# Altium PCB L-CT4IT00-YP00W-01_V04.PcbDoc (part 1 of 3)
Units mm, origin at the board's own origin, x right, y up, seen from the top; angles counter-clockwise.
Board outline 45 x 50 mm, 6 copper layers (Top Layer, GND1, Signal3, Siganl4, GND5, Bottom Layer), stack 1.57 mm thick; 213 components, 129 nets, 723 pads, 573 vias.
Unrouted connection lines stored in the file: 173.
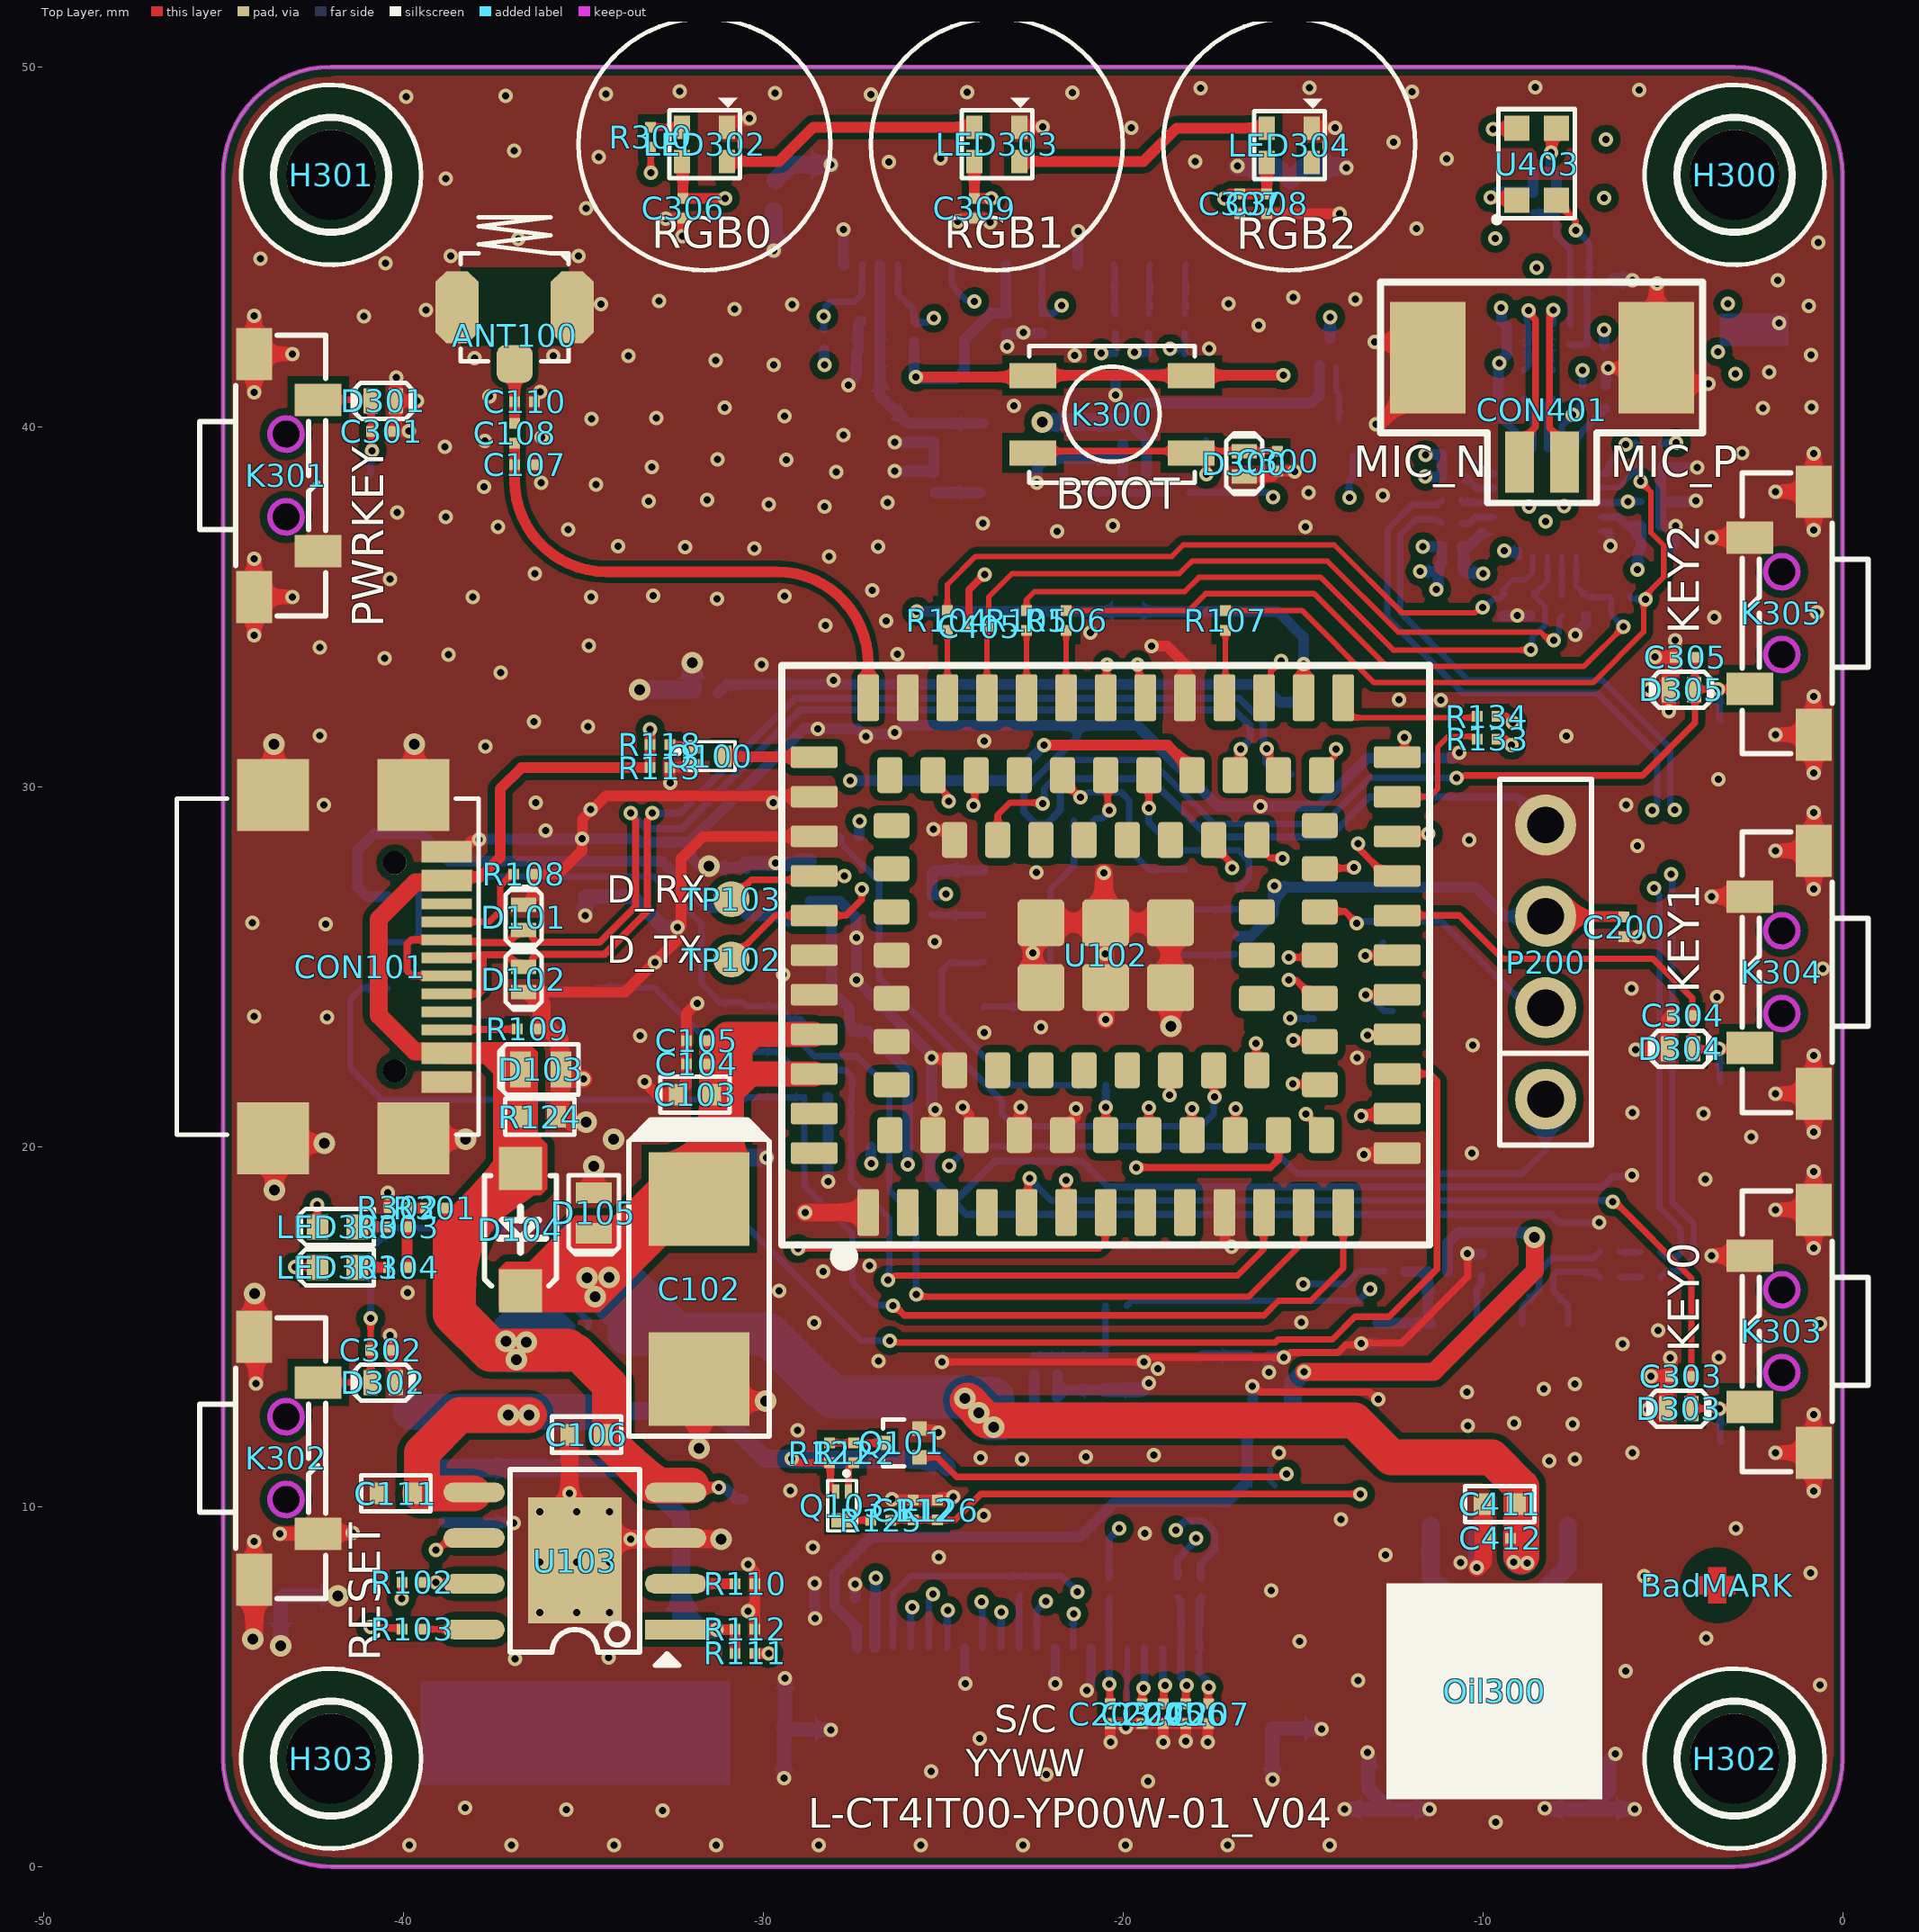
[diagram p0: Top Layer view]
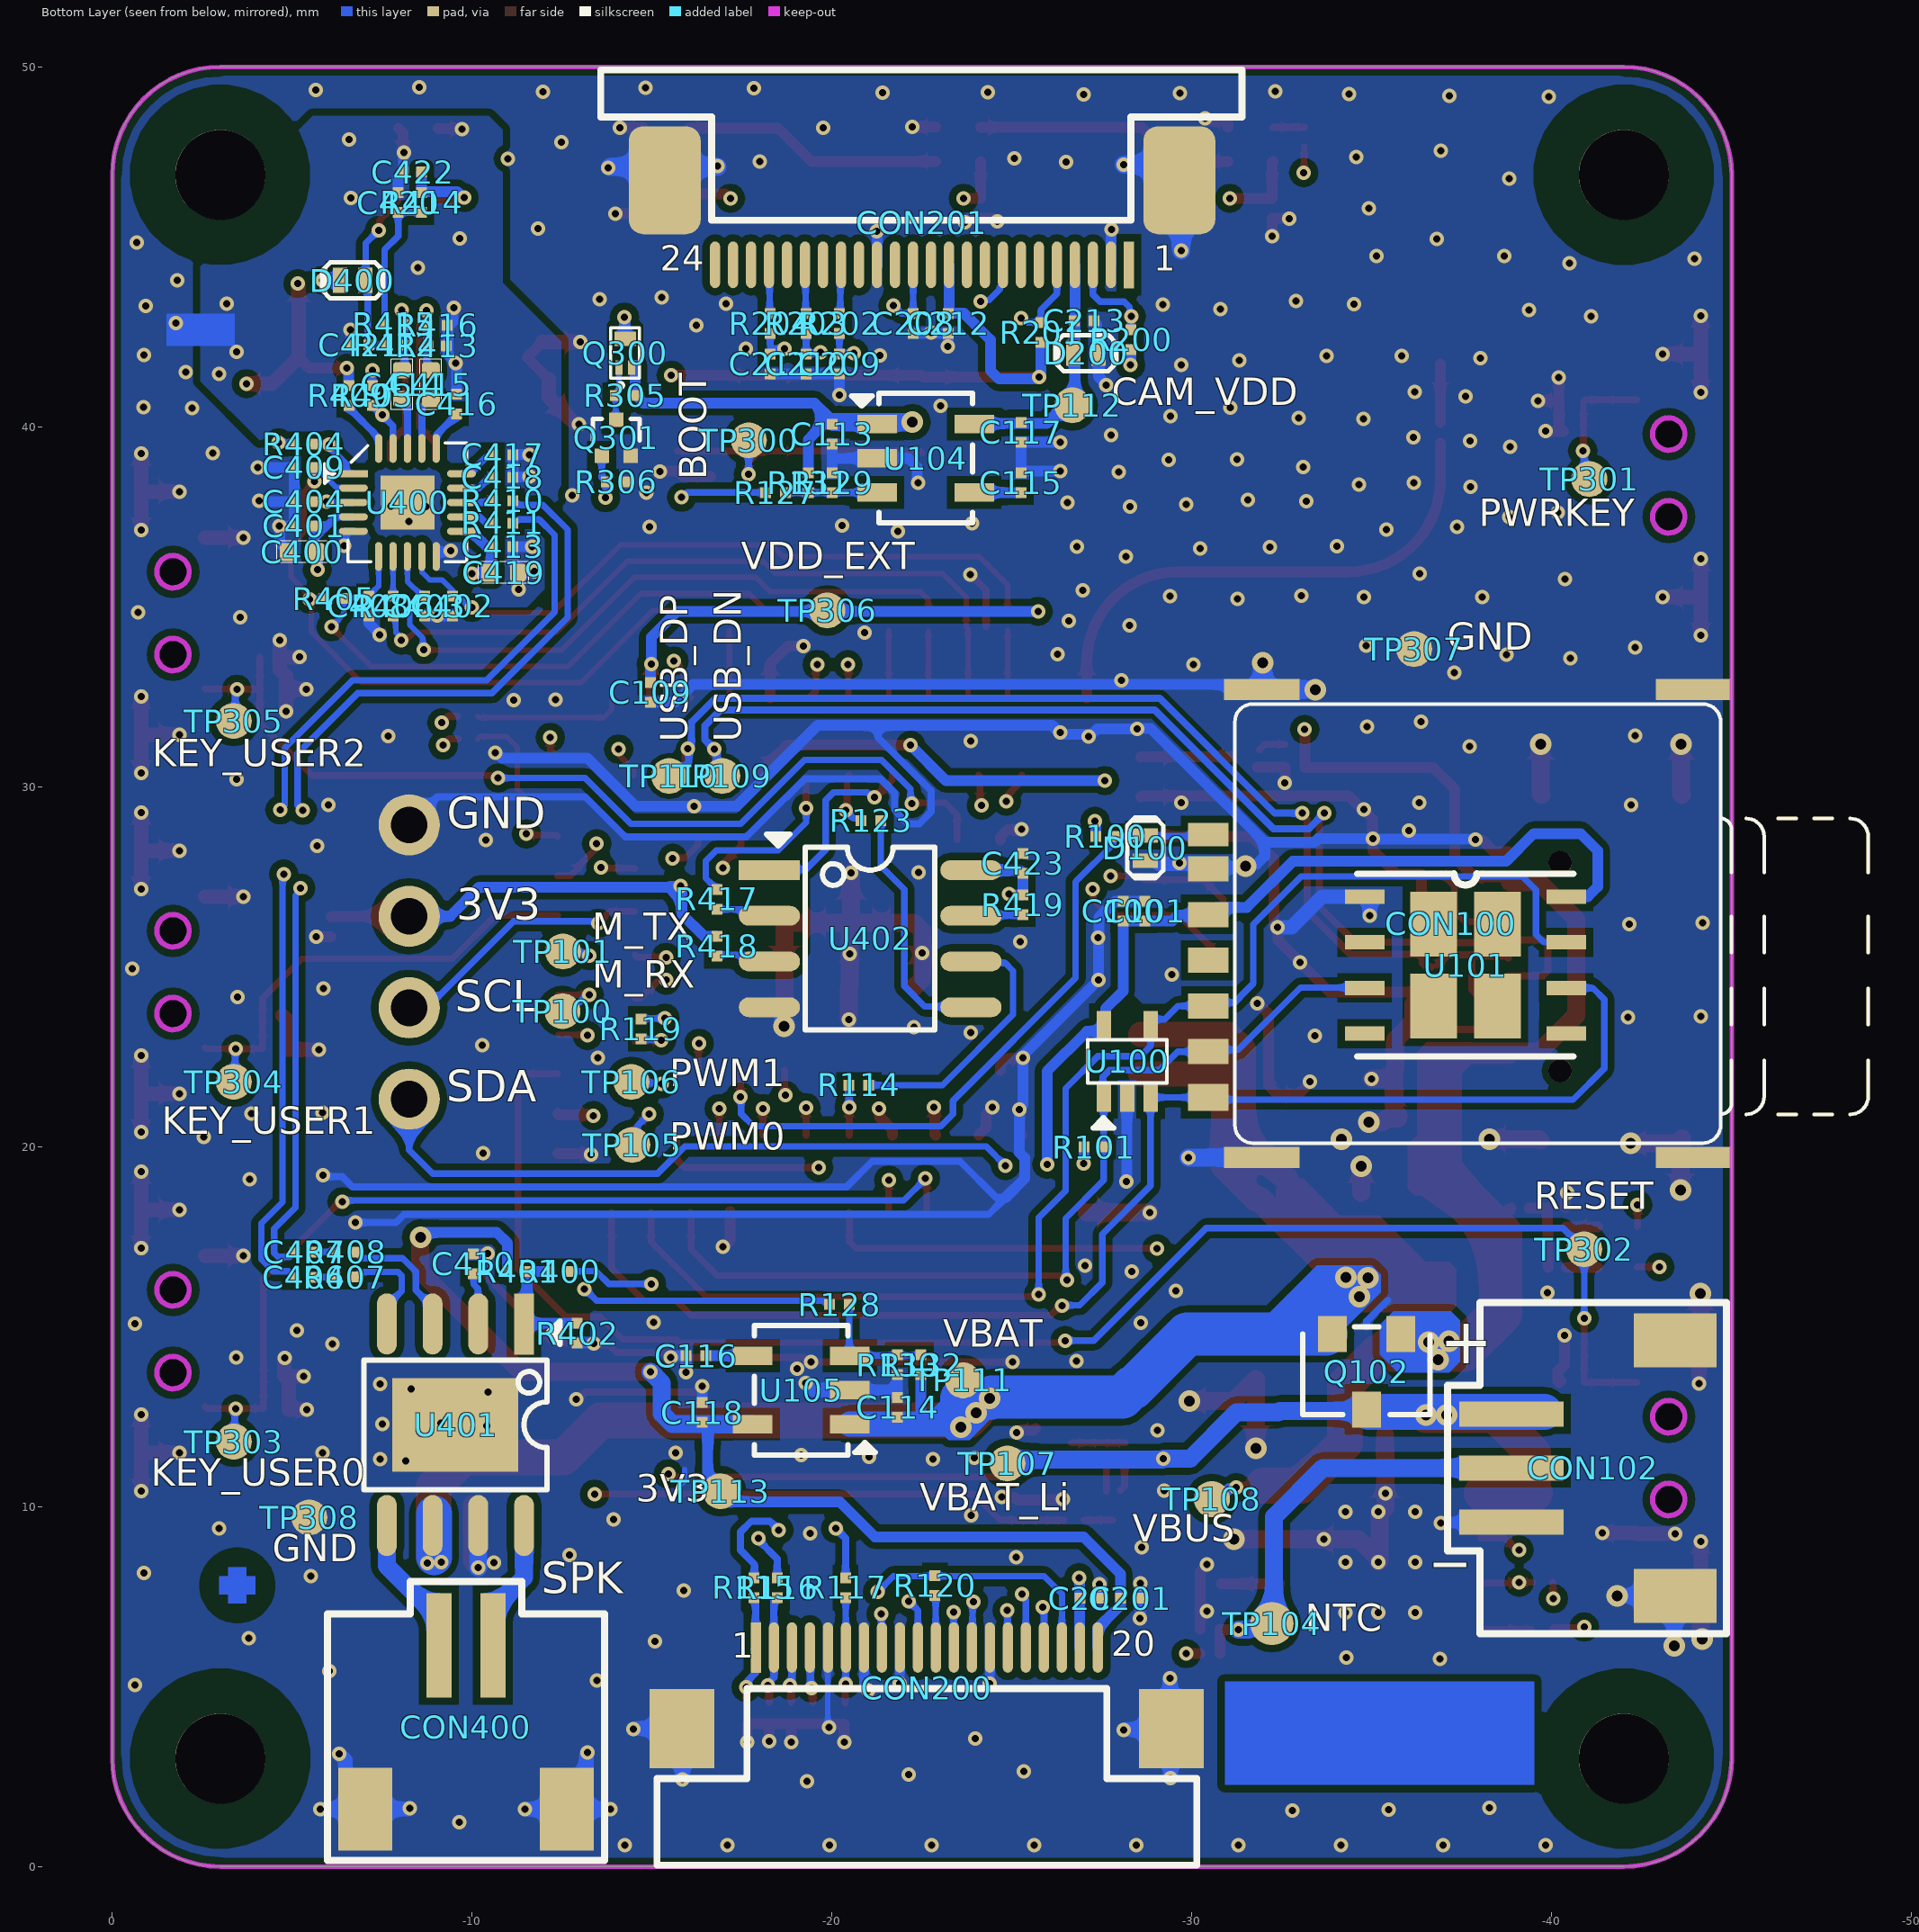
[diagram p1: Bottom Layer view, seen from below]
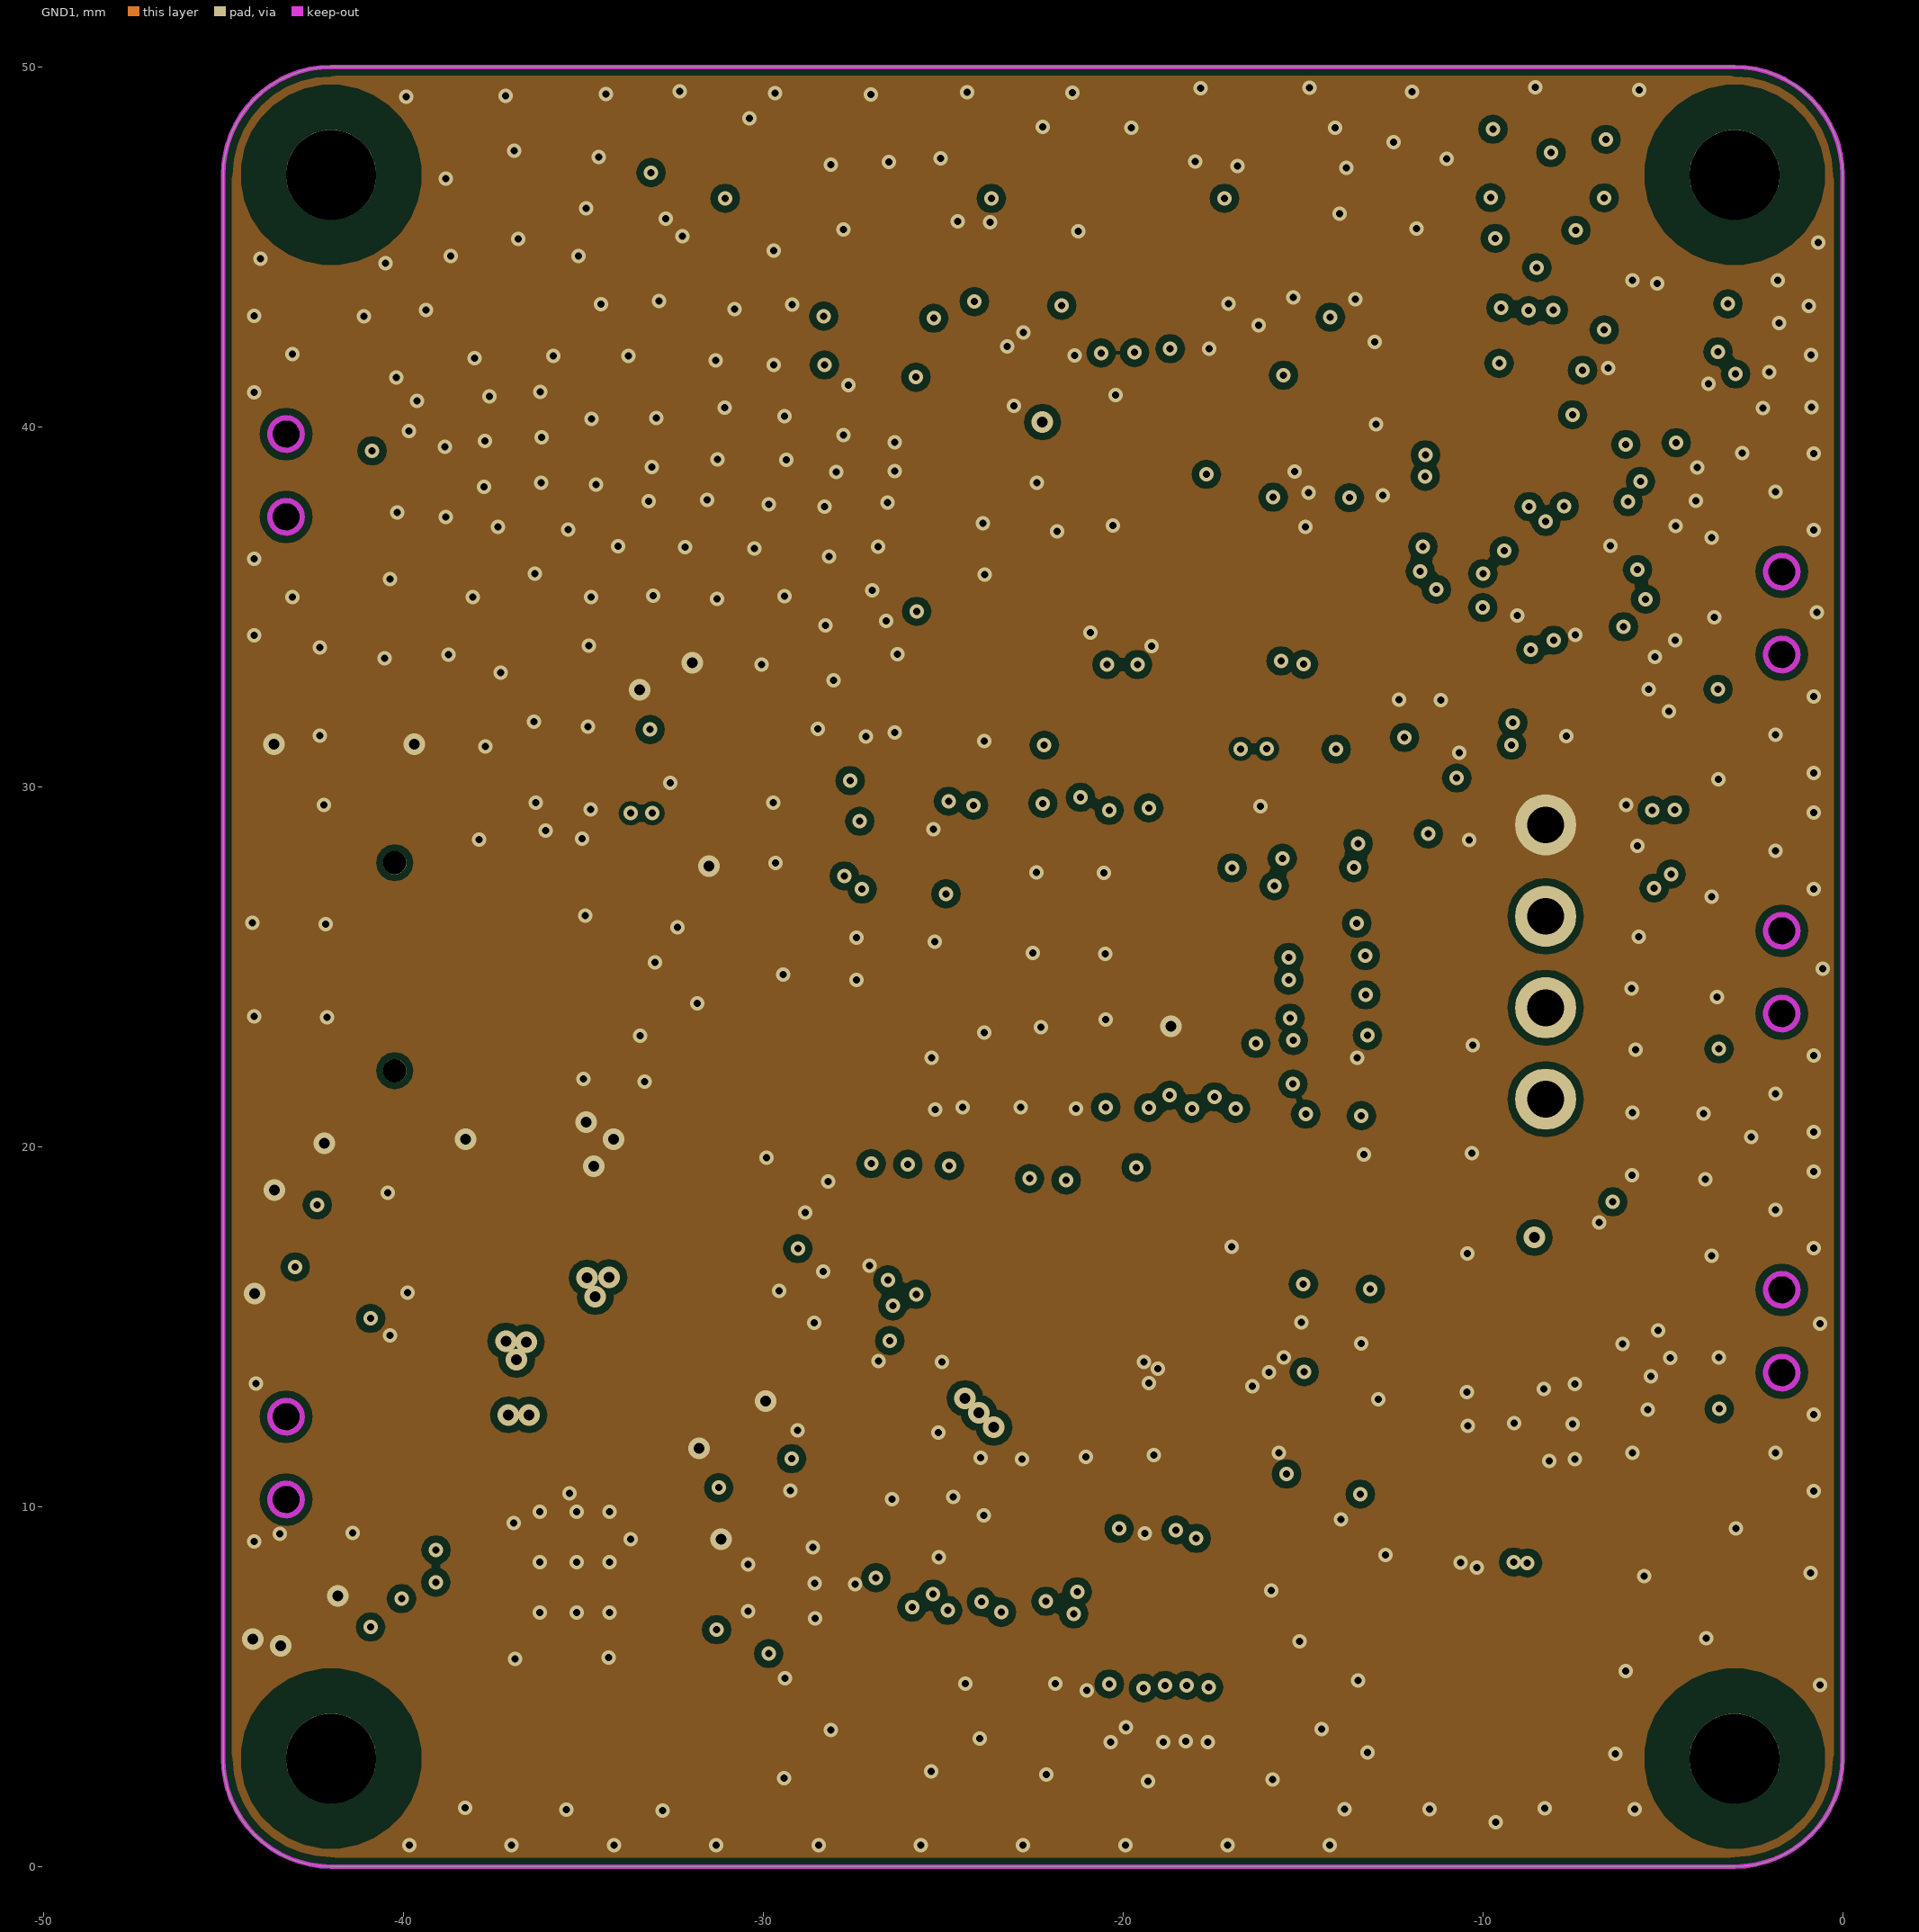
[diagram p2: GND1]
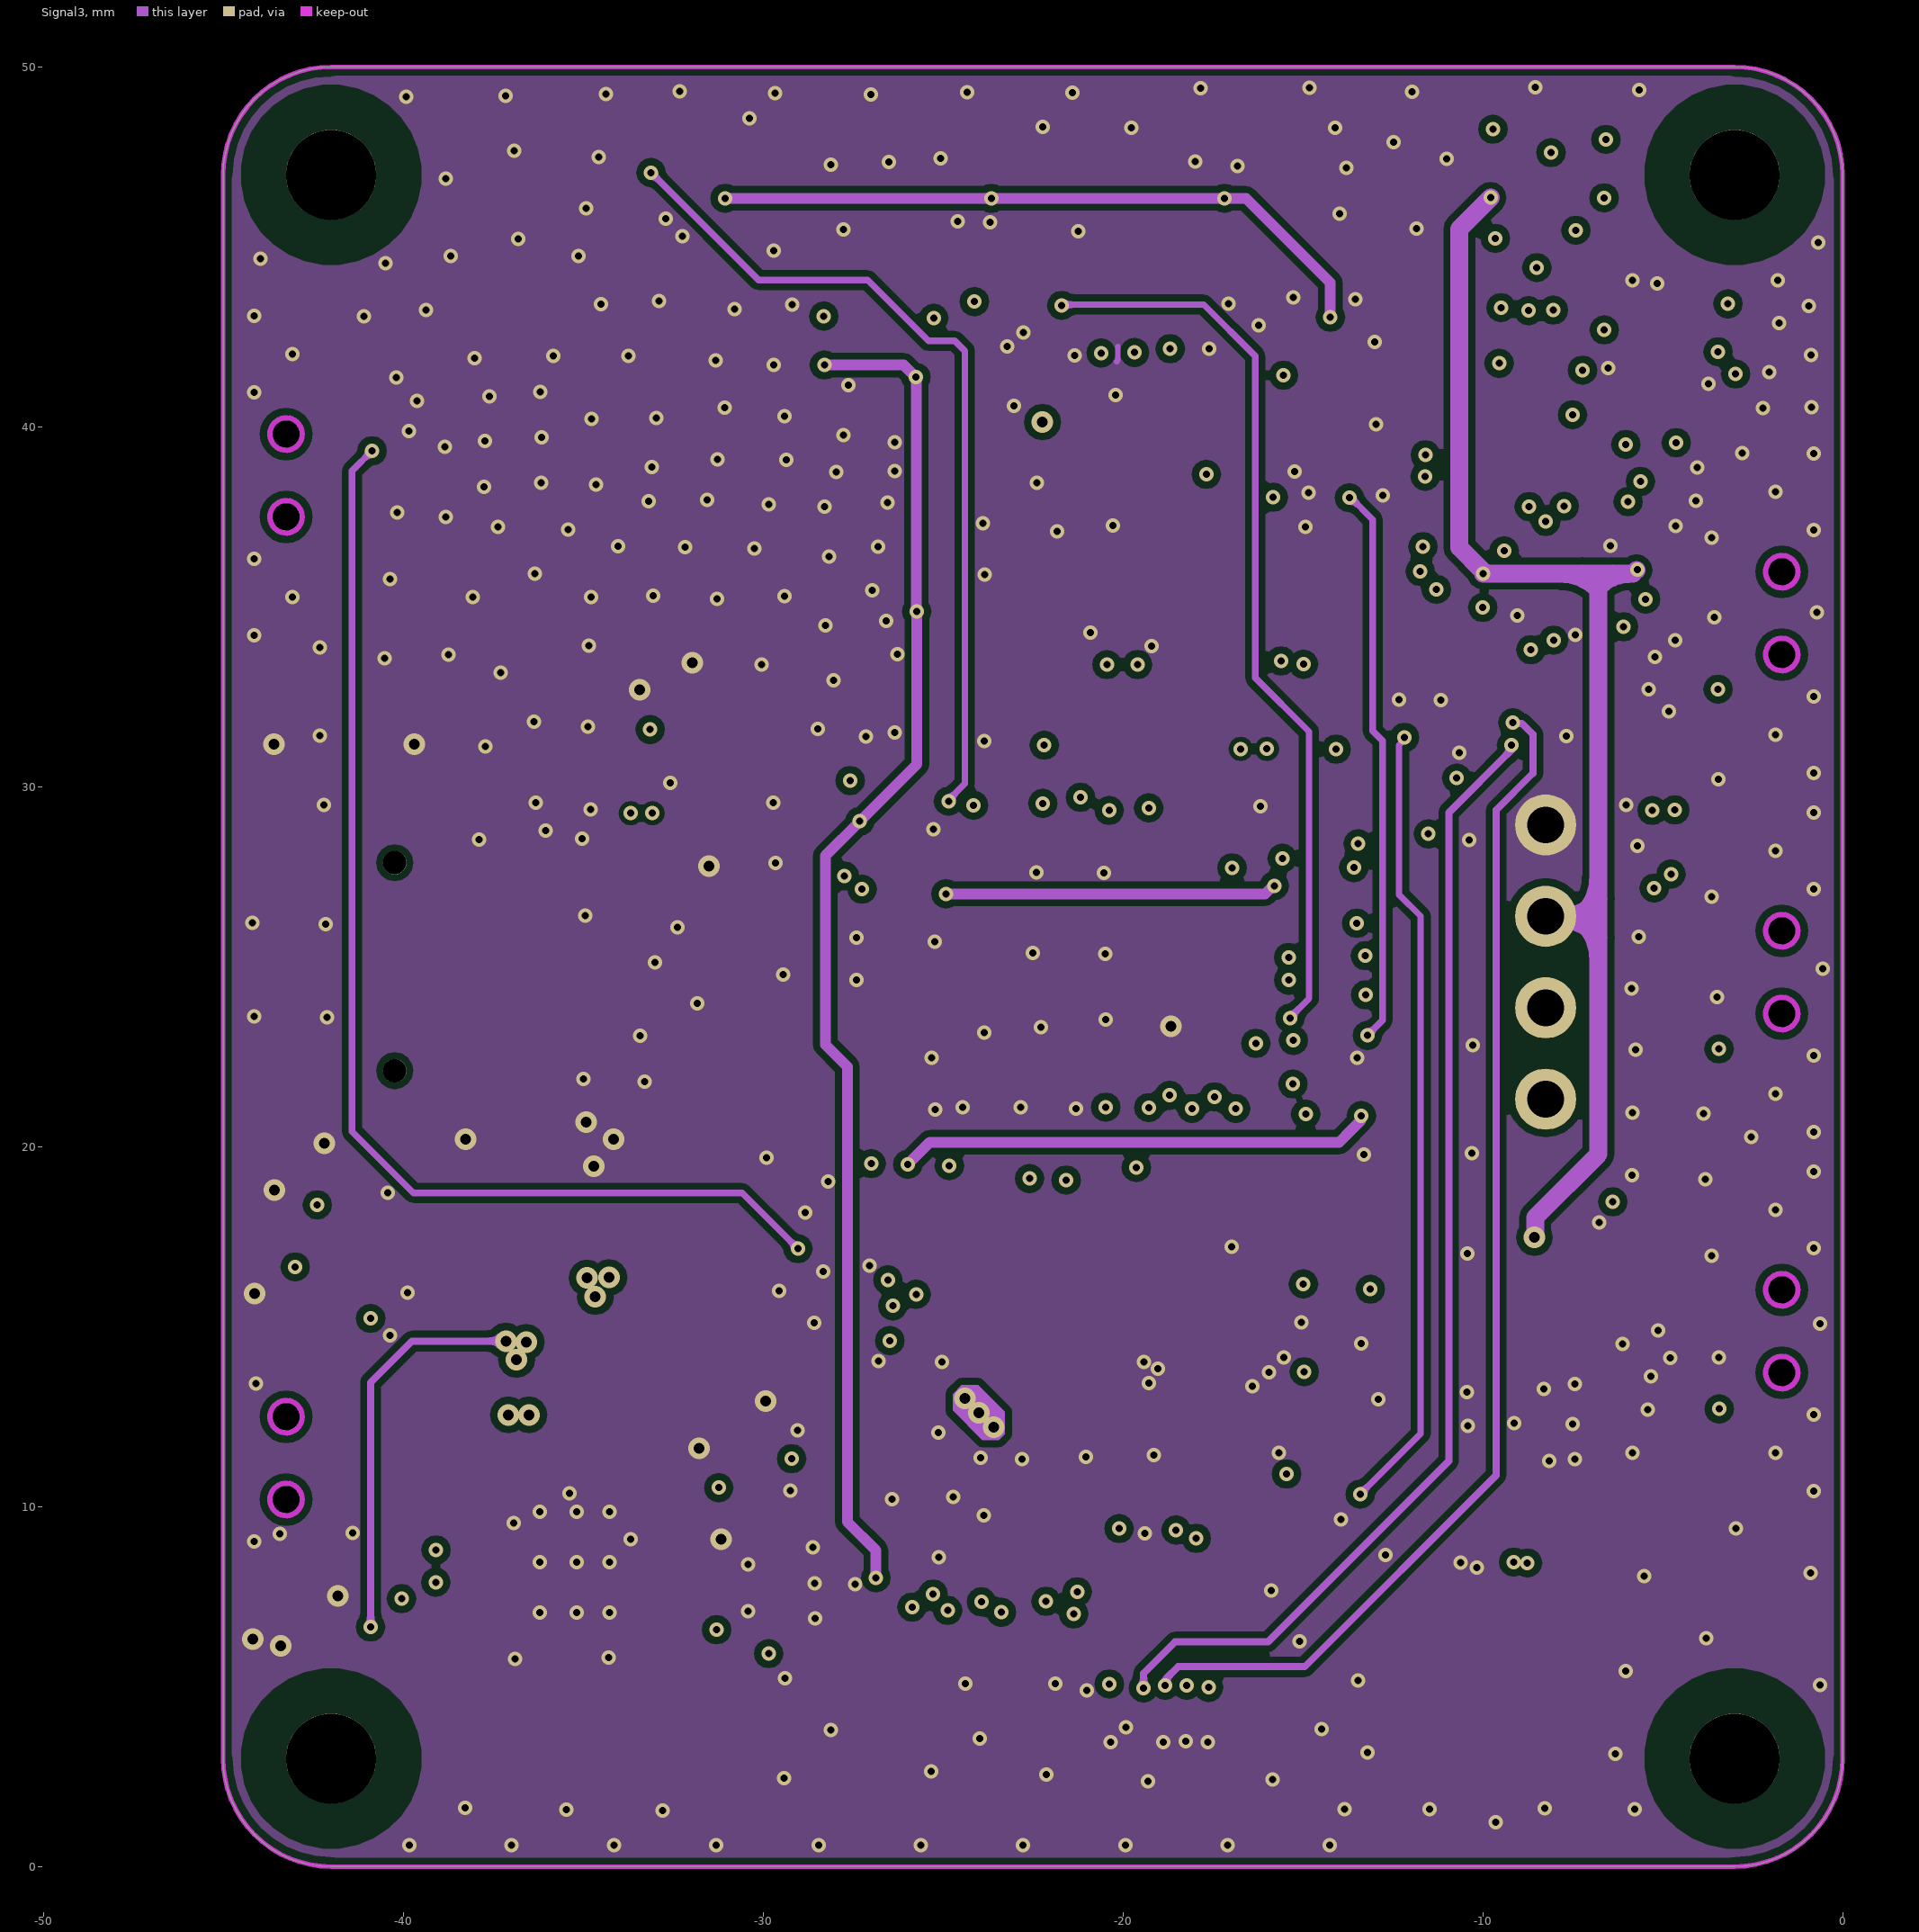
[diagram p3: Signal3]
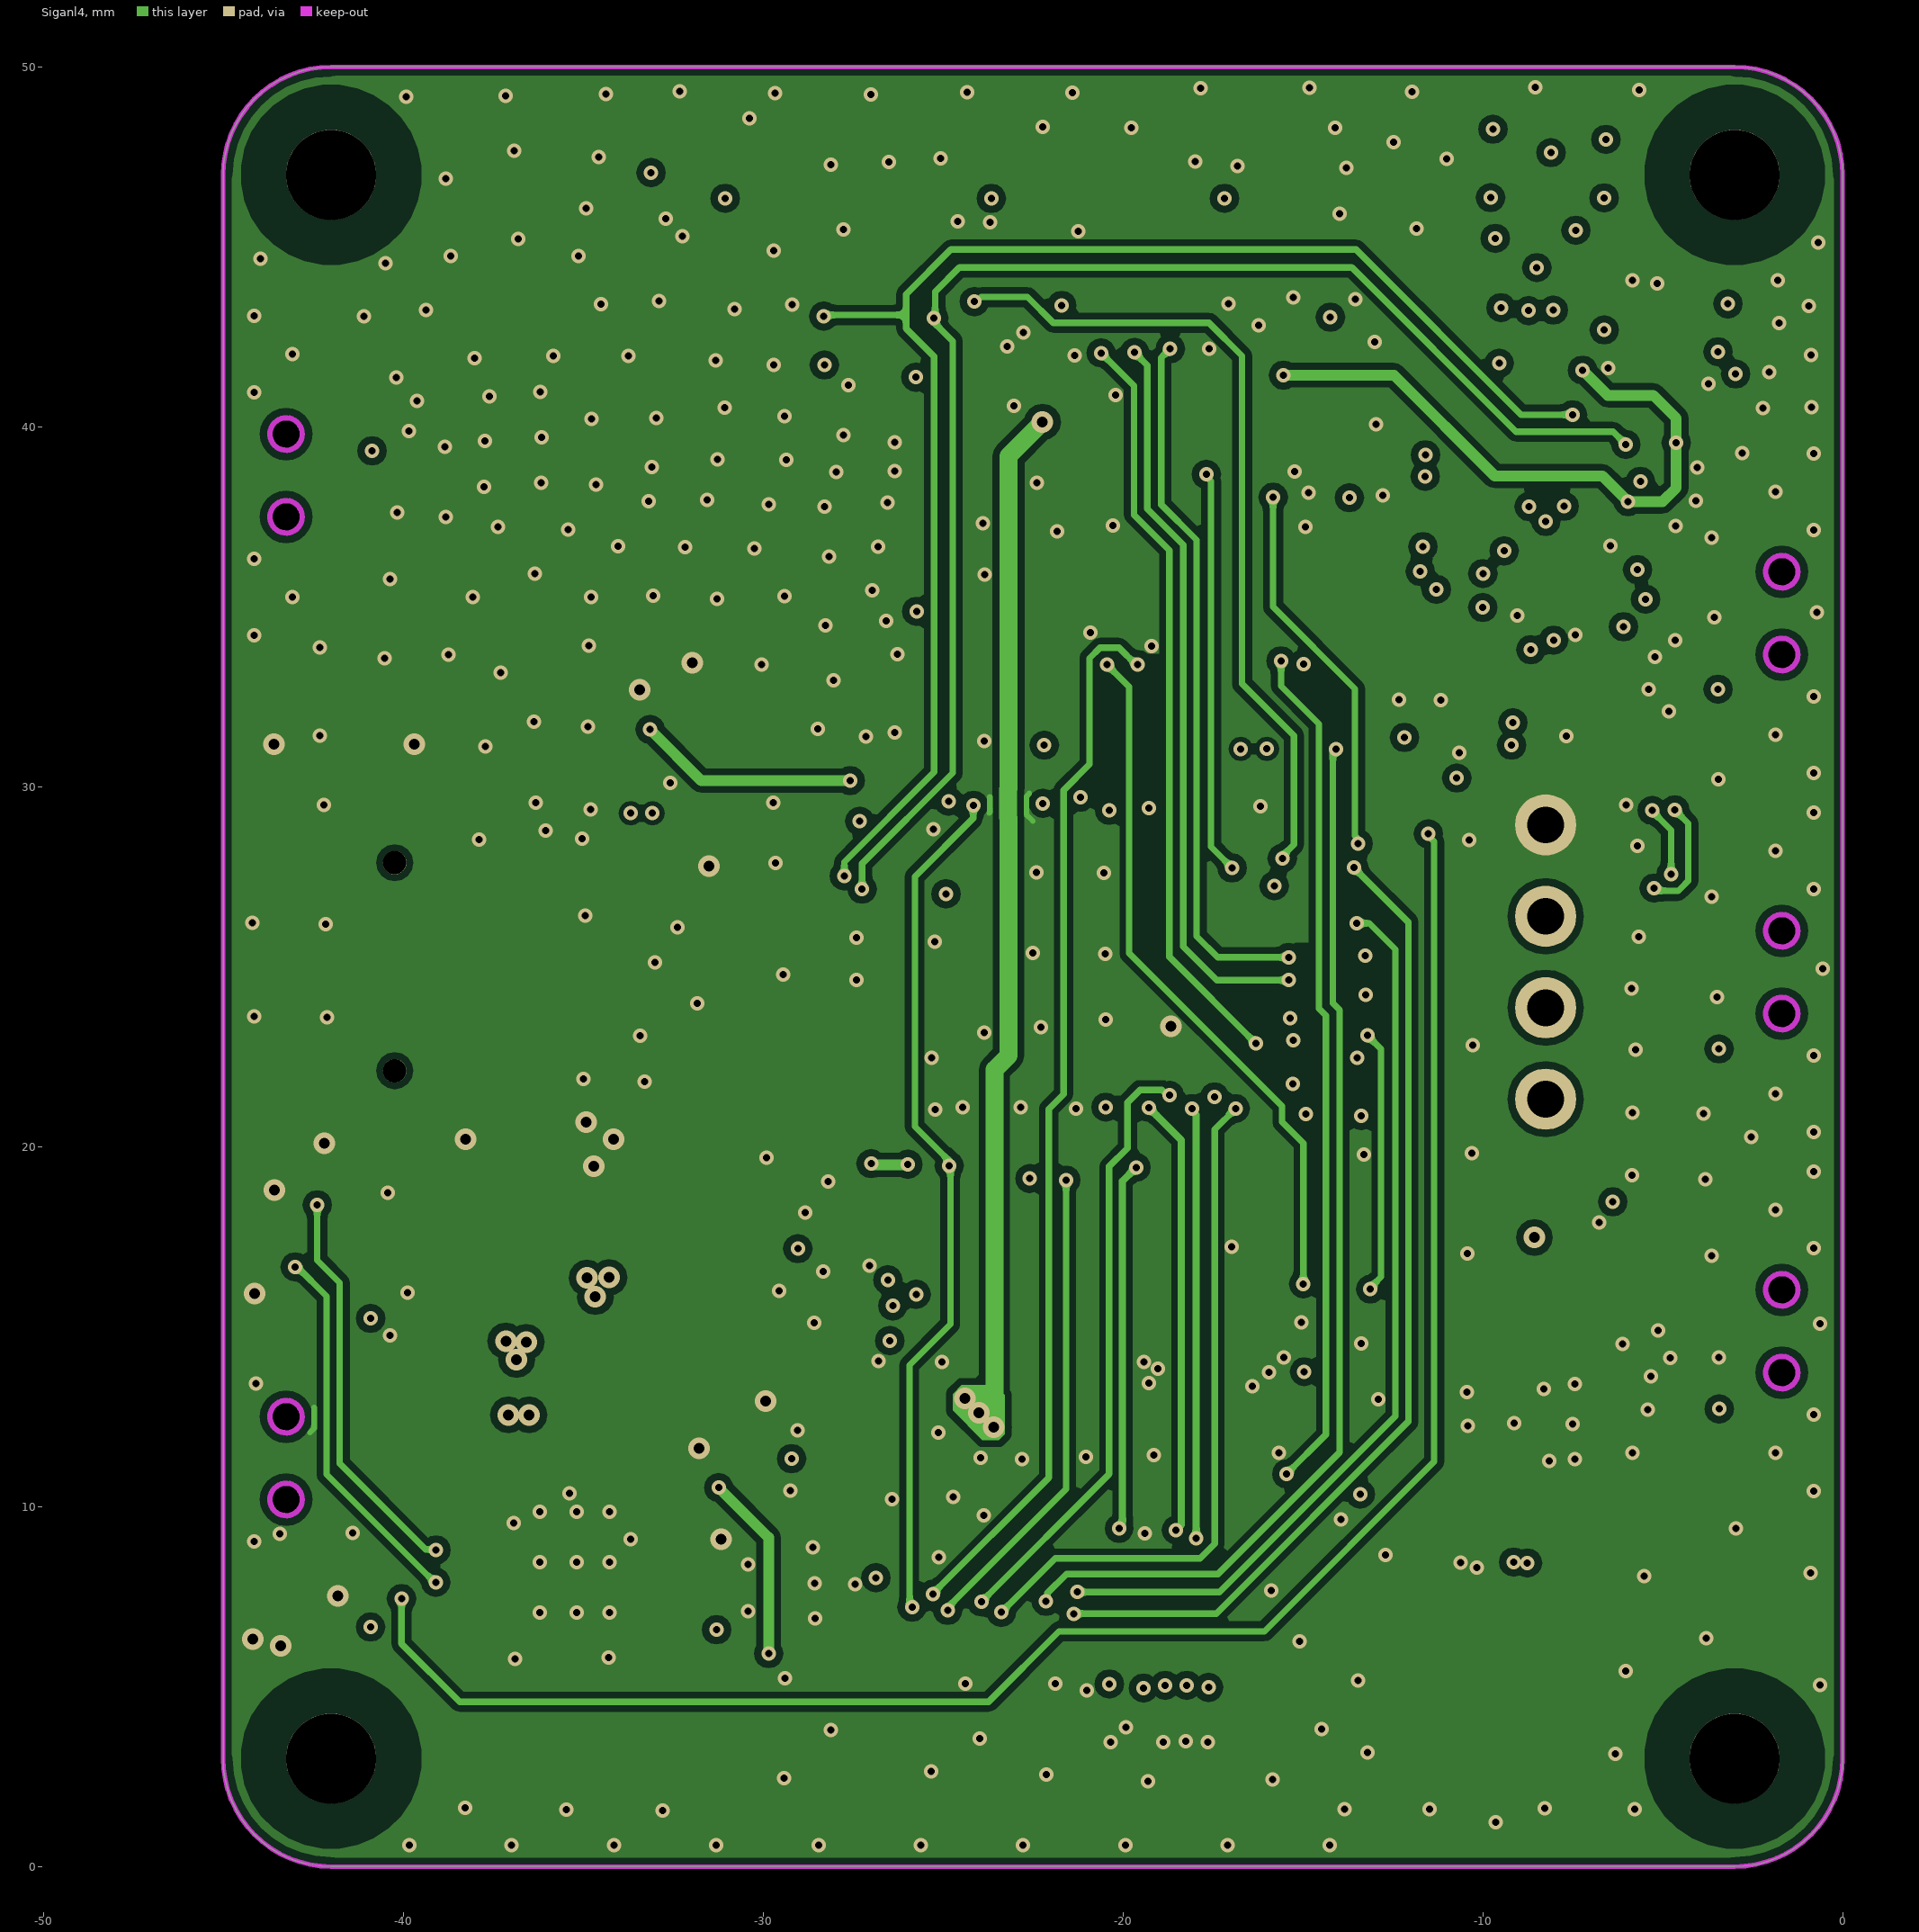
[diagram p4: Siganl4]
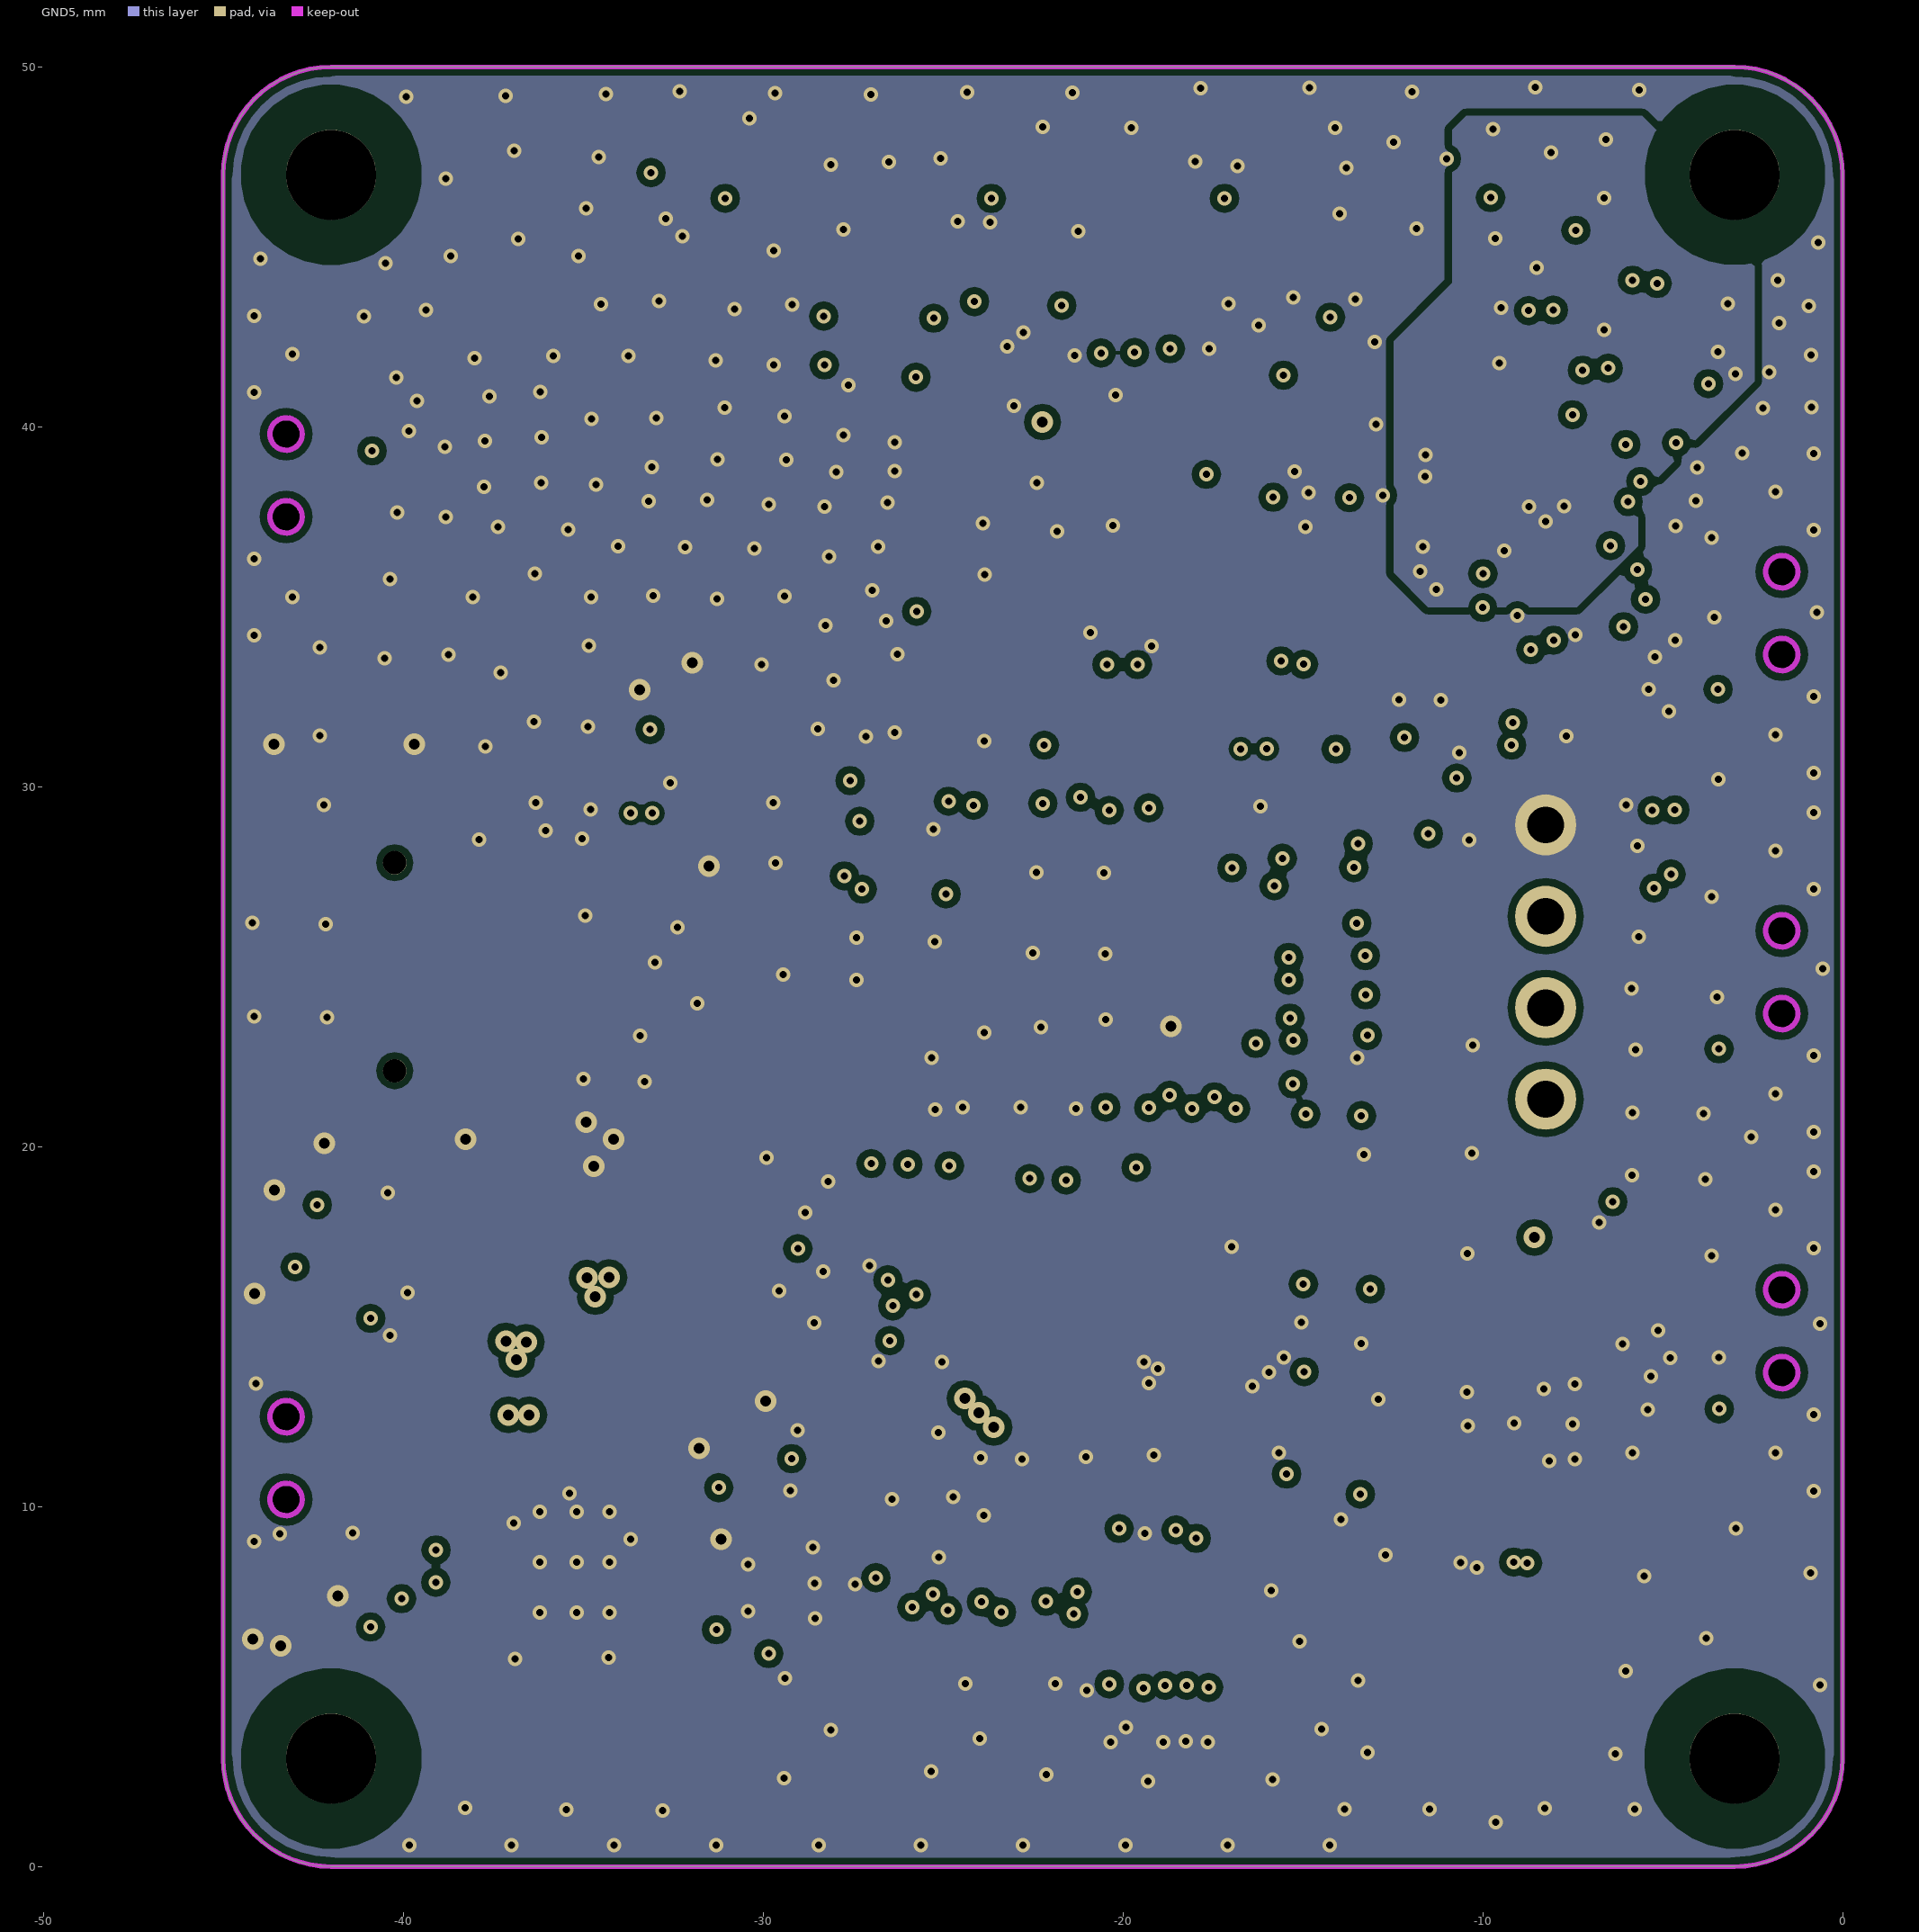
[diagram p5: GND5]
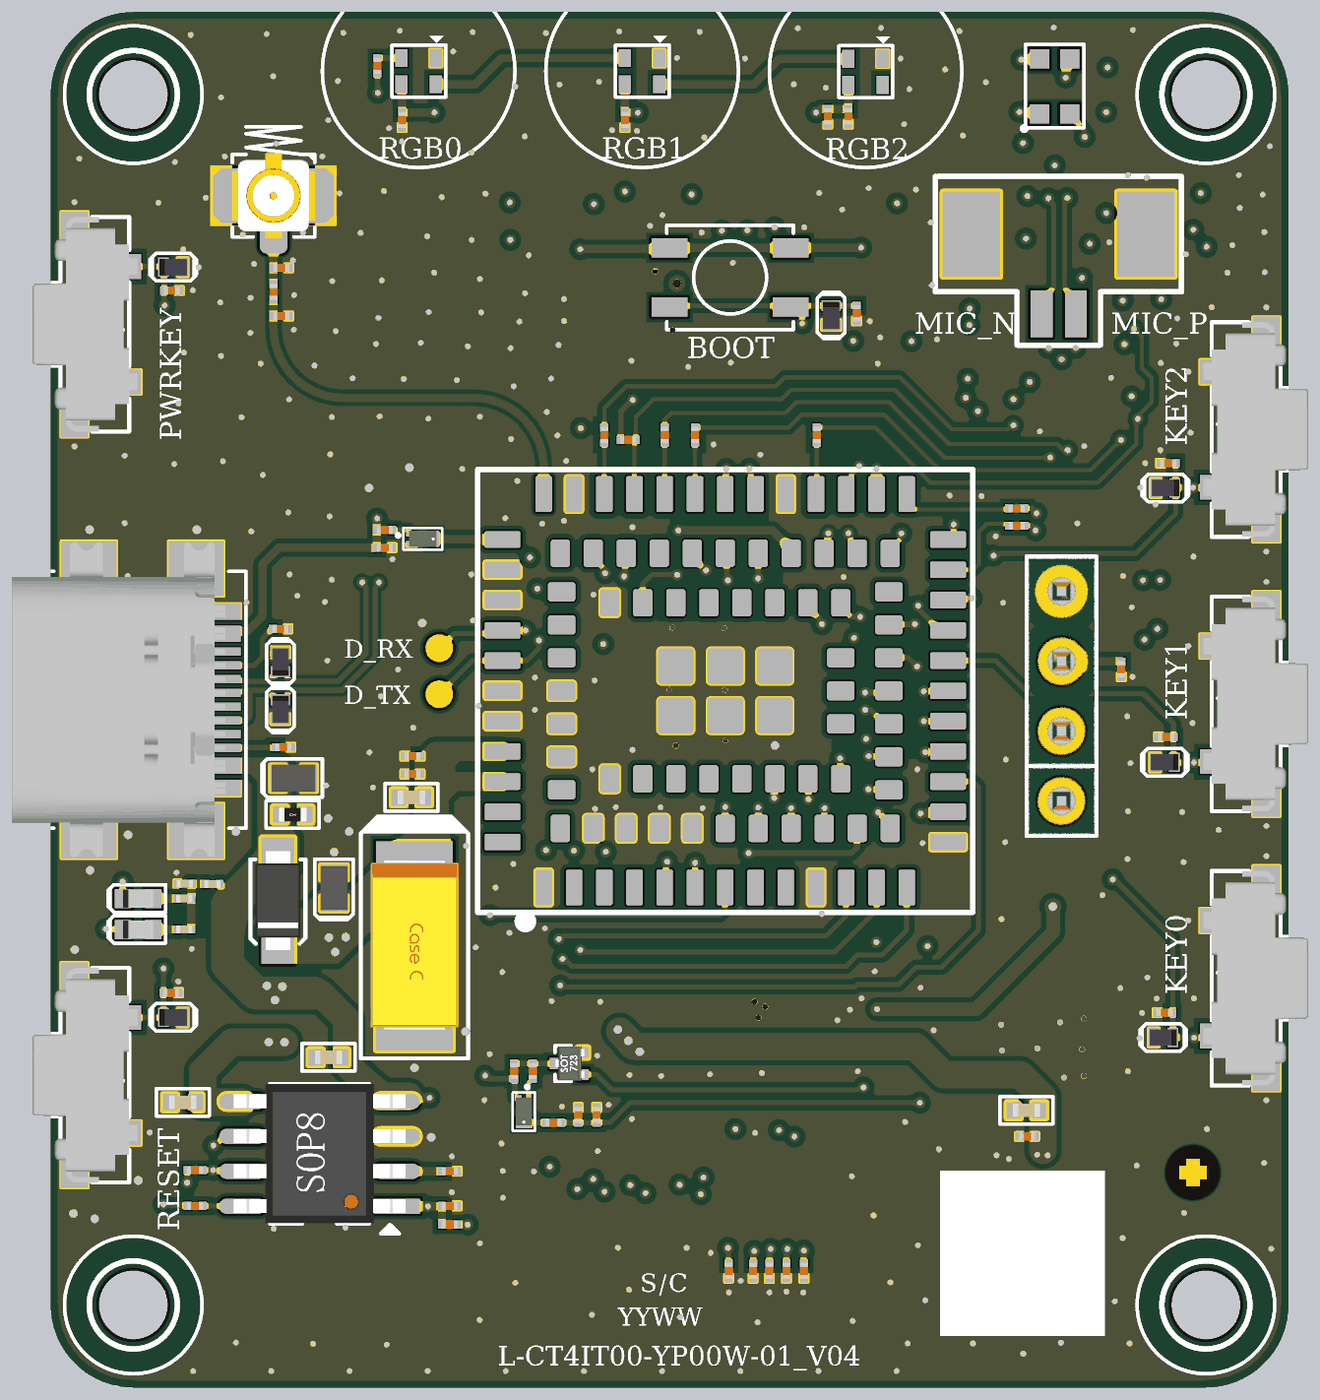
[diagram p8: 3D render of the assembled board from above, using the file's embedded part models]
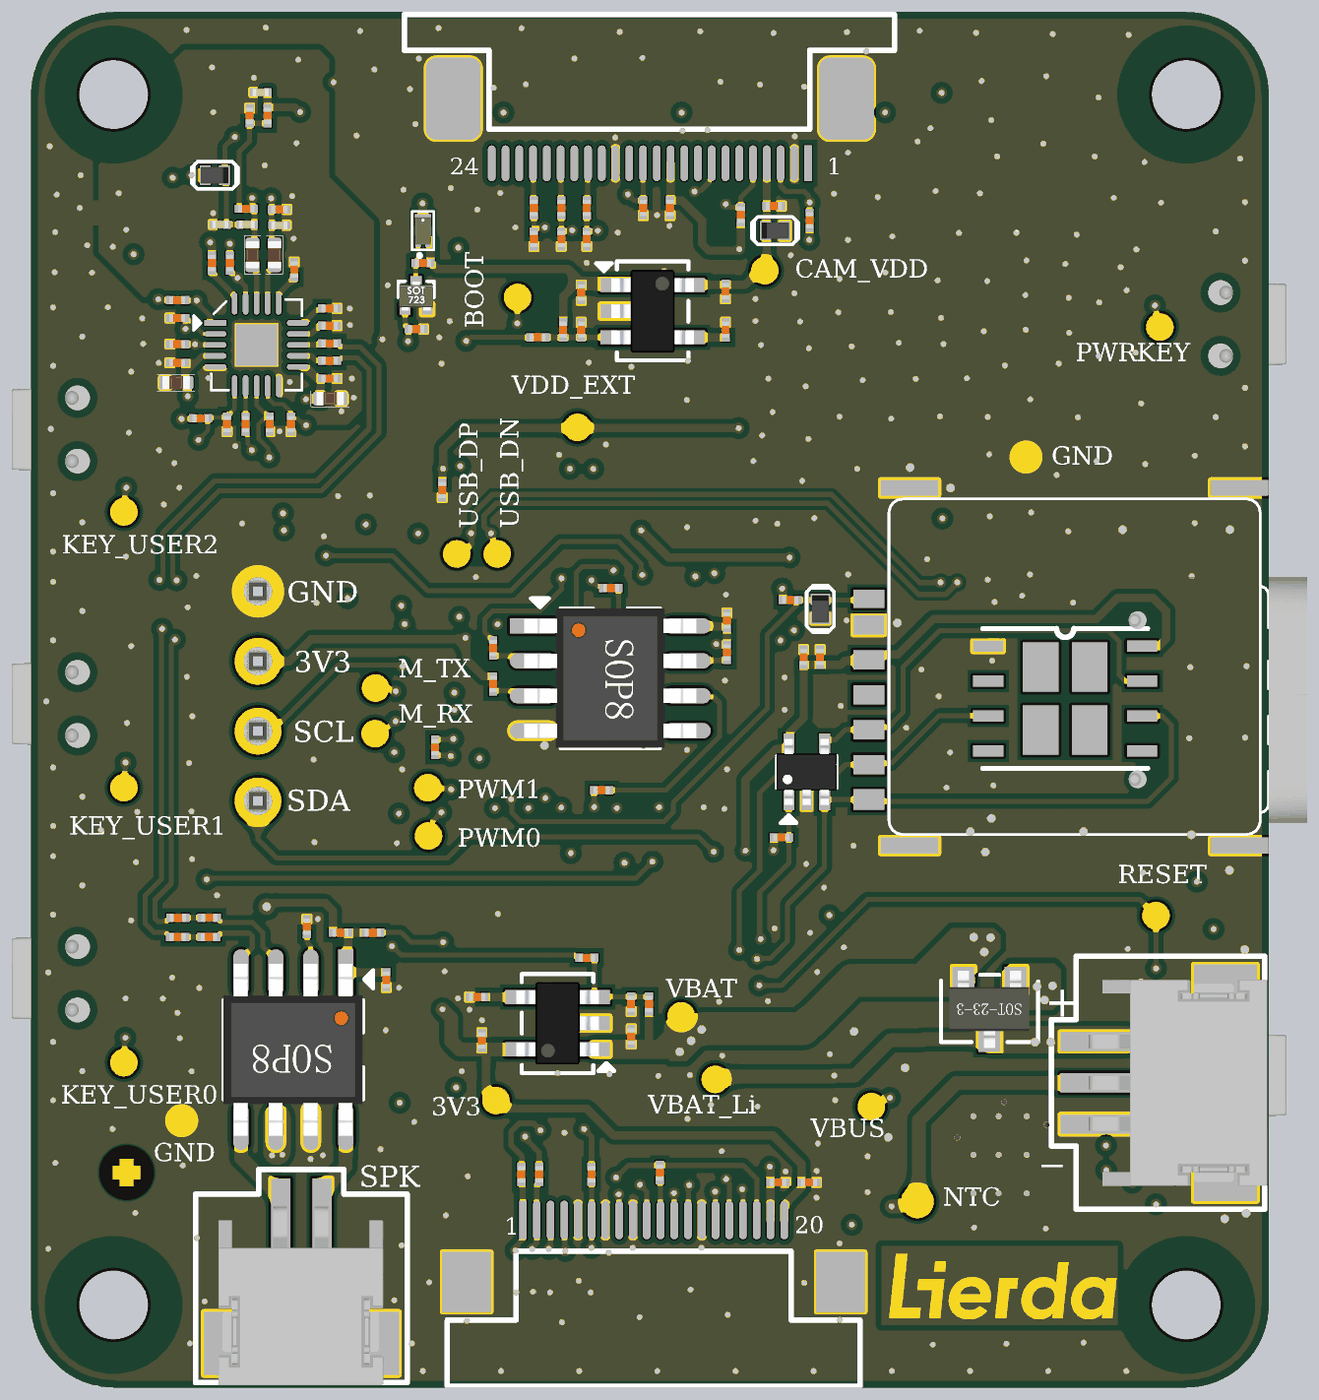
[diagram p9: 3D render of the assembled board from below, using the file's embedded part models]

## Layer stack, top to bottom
Top Solder: solder mask 0.015, SM-001, Dk 4
Top Layer: signal copper 0.035
Dielectric 4: prepreg 0.1, PP-006, Dk 4.1
GND1: signal copper 0.035
Dielectric 2: prepreg 0.18, PP-021, Dk 4.7
Signal3: signal copper 0.035
Dielectric 1: core 0.8, Core-040, Dk 4.6
Siganl4: signal copper 0.035
Dielectric 3: prepreg 0.18, PP-021, Dk 4.7
GND5: signal copper 0.035
Dielectric 5: prepreg 0.1, PP-006, Dk 4.1
Bottom Layer: signal copper 0.035
Bottom Solder: solder mask 0.015, SM-001, Dk 4

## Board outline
-42,0 cw(c-42,3) -45,3 -45,47 cw(c-42,47) -42,50 -3,50 cw(c-3,47) 0,47 0,3 cw(c-3,3) -3,0
cut-out: -1.687,35.525 cw(c-1.687,35.975) -2.137,35.975 cw(c-1.687,35.975) -1.687,36.425 cw(c-1.687,35.975) -1.237,35.975 cw(c-1.687,35.975)
cut-out: -1.687,33.225 cw(c-1.687,33.675) -2.137,33.675 cw(c-1.687,33.675) -1.687,34.125 cw(c-1.687,33.675) -1.237,33.675 cw(c-1.687,33.675)
cut-out: -1.687,23.25 cw(c-1.687,23.7) -2.137,23.7 cw(c-1.687,23.7) -1.687,24.15 cw(c-1.687,23.7) -1.237,23.7 cw(c-1.687,23.7)
cut-out: -1.687,25.55 cw(c-1.687,26) -2.137,26 cw(c-1.687,26) -1.687,26.45 cw(c-1.687,26) -1.237,26 cw(c-1.687,26)
cut-out: -2.137,16.025 ccw(c-1.687,16.025) -1.687,15.575 ccw(c-1.687,16.025) -1.237,16.025 ccw(c-1.687,16.025) -1.687,16.475 ccw(c-1.687,16.025)
cut-out: -2.137,13.725 ccw(c-1.687,13.725) -1.687,13.275 ccw(c-1.687,13.725) -1.237,13.725 ccw(c-1.687,13.725) -1.687,14.175 ccw(c-1.687,13.725)
cut-out: -43.25,9.75 cw(c-43.25,10.2) -43.7,10.2 cw(c-43.25,10.2) -43.25,10.65 cw(c-43.25,10.2) -42.8,10.2 cw(c-43.25,10.2)
cut-out: -43.25,12.05 cw(c-43.25,12.5) -43.7,12.5 cw(c-43.25,12.5) -43.25,12.95 cw(c-43.25,12.5) -42.8,12.5 cw(c-43.25,12.5)
cut-out: -43.25,37.05 cw(c-43.25,37.5) -43.7,37.5 cw(c-43.25,37.5) -43.25,37.95 cw(c-43.25,37.5) -42.8,37.5 cw(c-43.25,37.5)
cut-out: -43.25,39.35 cw(c-43.25,39.8) -43.7,39.8 cw(c-43.25,39.8) -43.25,40.25 cw(c-43.25,39.8) -42.8,39.8 cw(c-43.25,39.8)

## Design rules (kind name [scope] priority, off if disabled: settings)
Clearance 3W [InNetClass('3W-1') vs OnLayer('Top Layer')] p1: gap=0.18 ignorepadtopadclearanceinfootprint=FALSE except(0.25: SMDPad-Fill SMDPad-Poly SMDPad-Region; 0.3: Arc-Arc Arc-Track Track-Track)
Clearance ISIVA [IsVia vs IsVia] p2: gap=0.2 ignorepadtopadclearanceinfootprint=TRUE
Clearance RF [InNetClass('RF')] p3: gap=0.15 ignorepadtopadclearanceinfootprint=FALSE
Clearance USB [InDifferentialPair('USB_D')] p4: gap=0.13 ignorepadtopadclearanceinfootprint=FALSE
Clearance USB1 [IsTrack > InDifferentialPair('USB_D')] p5: gap=0.18 ignorepadtopadclearanceinfootprint=FALSE
Clearance ALL [All] p6: gap=0.18 ignorepadtopadclearanceinfootprint=FALSE except(0.2: Arc-Fill Arc-Poly Arc-Region Track-Fill Track-Poly Track-Region SMDPad-Fill SMDPad-Poly SMDPad-Region THPad-Fill THPad-Poly THPad-Region Via-Fill Via-Poly Via-Region Fill-Fill Fill-Poly Fill-Region Poly-Poly Poly-Region Region-Region)
DiffPairsRouting [All] p1: maxlimit=0.254 minlimit=0.13 mostfreqgap=0.13 toplayer_minwidth=0.2 toplayer_maxwidth=0.25 toplayer_prefwidth=0.25 midlayer1_minwidth=0.2 midlayer1_maxwidth=0.25 midlayer1_prefwidth=0.25 midlayer2_minwidth=0.2 midlayer2_maxwidth=0.25 midlayer2_prefwidth=0.25 midlayer3_minwidth=0.2 midlayer3_maxwidth=0.25 midlayer3_prefwidth=0.25 midlayer4_minwidth=0.2 midlayer4_maxwidth=0.25 midlayer4_prefwidth=0.25 bottomlayer_minwidth=0.2 bottomlayer_maxwidth=0.25 bottomlayer_prefwidth=0.25 maxuncoupledlength=12.7
Height [All] p1 off: minheight=0 maxheight=25.4 prefheight=12.7
HoleToHoleClearance [All] p1 off: gap=0.4 allowstackedmicrovias=TRUE
LayerPairs [All] p1 off: enforce=TRUE
MinimumSolderMaskSliver [All] p1 off: minsoldermaskwidth=0.254
PolygonConnect PolygonConnect_1 [All] p1: connectstyle=Direct reliefconductorwidth=0.254 reliefentries=4 polygonreliefangle="90 Angle" airgapwidth=0.254
PolygonConnect [All] p2: connectstyle=Relief reliefconductorwidth=0.254 reliefentries=4 polygonreliefangle="90 Angle" airgapwidth=0.254
RoutingVias [All] p1: holewidth=0.3 width=0.5 viastyle="Through Hole" minholewidth=0.2 minwidth=0.4 maxholewidth=0.4 maxwidth=0.7
SilkToSilkClearance [All] p1 off: silktosilkclearance=0.254
SilkToSolderMaskClearance [IsPad] p1 off: minsilkscreentomaskgap=0.254 clearancetoexposedcopper=TRUE
SolderMaskExpansion [All] p1: expansion=0.102 istentingtop=FALSE
SupplyNets "Schematic Supply Nets_8" [InNet('VCC_RGB')] p1: voltage=0.000
SupplyNets "Schematic Supply Nets_7" [InNet('3V3')] p2: voltage=0.000
SupplyNets "Schematic Supply Nets_6" [InNet('VBUS')] p3: voltage=0.000
SupplyNets "Schematic Supply Nets_5" [InNet('AGND')] p4: voltage=0.000
SupplyNets "Schematic Supply Nets_4" [InNet('VBAT_Li')] p5: voltage=0.000
SupplyNets "Schematic Supply Nets_3" [InNet('GND')] p6: voltage=0.000
SupplyNets "Schematic Supply Nets_2" [InNet('VDD_EXT')] p7: voltage=0.000
SupplyNets "Schematic Supply Nets_1" [InNet('CAM_VDD')] p8: voltage=0.000
SupplyNets "Schematic Supply Nets" [InNet('VBAT')] p9: voltage=0.000
UnRoutedNet [All] p1: checkbadconnections=TRUE
Width [All] p1: maxlimit=5 minlimit=0.152 preferedwidth=0.2 minimp=50.000000 maximp=50.000000 favimp=50.000000
22 further rules are at their usual default settings.

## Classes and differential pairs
net class 3W-1: CODEC_I2S_BCLK CODEC_I2S_DIN CODEC_I2S_DOUT CODEC_I2S_LRCK CODEC_I2S_MCLK NetR104_1 NetR105_1 NetR106_1 NetR107_1
net class RF: NetANT100_1 NetC107_2
differential pair USB_D: +USB_D_P -USB_D_N

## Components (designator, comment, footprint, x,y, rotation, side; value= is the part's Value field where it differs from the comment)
ANT100 "IPEX-1" IPX_U.FL-R-SMT-1 -36.9,43.325 r90 top
BadMARK "BadMARK" "Bad Mark" -3.476,7.812 r90 top
C100 "1uF/6.3V" 0201_0.25D -28.088,26.55 r270 bottom
C101 "0.1uF" 0201_0.25D -28.688,26.55 r270 bottom
C102 "220uF/C型" 6032-TC -31.775,16.05 r90 top
C103 "10uF/10V" 0402C_0.4D -31.887,21.45 r0 top
C104 "0.1uF" 0201_0.25D -31.85,22.3 r0 top
C105 "33pF" 0201_0.25D -31.85,22.95 r0 top
C106 "10uF/10V" 0402C_0.4D -34.905,12.001 r0 top
C107 "NC" 0201_0.25D -36.625,38.95 r180 top
C108 "100pF" 0201_0.25D -36.9,39.825 r270 top
C109 "1uF/10V" 0201_0.25D -14.95,32.625 r90 bottom
C110 "NC" 0201_0.25D -36.625,40.7 r180 top
C111 "10uF/10V" 0402C_0.4D -40.203,10.367 r0 top
C112 "NC/0.1uF/10V" 0201_0.25D -25.819,9.905 r270 top
C113 "1uF/10V" 0201_0.25D -20,39.8 r90 bottom
C114 "1uF/10V" 0201_0.25D -21.821,12.76 r270 bottom
C115 "0.01uF" 0201_0.25D -25.25,38.45 r270 bottom
C116 "0.01uF" 0201_0.25D -16.218,14.191 r180 bottom
C117 "1uF/10V" 0201_0.25D -25.25,39.85 r90 bottom
C118 "1uF/10V" 0201_0.25D -16.393,12.616 r270 bottom
C200 "1uF/10V" 0201_0.25D -6.075,26.107 r90 top
C201 "1uF/10V" 0201_0.25D -28.287,7.454 r180 bottom
C202 "1uF/10V" 0201_0.25D -27.162,7.454 r180 bottom
C203 "NC" 0201_0.25D -20.353,4.241 r90 top
C204 "NC" 0201_0.25D -19.463,4.241 r90 top
C205 "NC" 0201_0.25D -18.873,4.241 r90 top
C206 "NC" 0201_0.25D -18.252,4.241 r90 top
C207 "NC" 0201_0.25D -17.614,4.241 r90 top
C208 "NC" 0201_0.25D -22.256,42.876 r90 bottom
C209 "NC" 0201_0.25D -20.206,41.751 r90 bottom
C210 "NC" 0201_0.25D -19.281,41.751 r90 bottom
C211 "NC" 0201_0.25D -18.282,41.751 r90 bottom
C212 "1uF/10V" 0201_0.25D -23.231,42.876 r270 bottom
C213 "1uF/6.3V" 0201_0.25D -27.006,42.951 r180 bottom
C300 "1uF/6.3V" 0201_0.25D -15.7,39.05 r90 top
C301 "1uF/6.3V" 0201_0.25D -40.6,39.875 r180 top
C302 "1uF/6.3V" 0201_0.25D -40.625,14.35 r180 top
C303 "1uF/6.3V" 0201_0.25D -4.5,13.625 r0 top
C304 "1uF/6.3V" 0201_0.25D -4.45,23.65 r0 top
C305 "1uF/6.3V" 0201_0.25D -4.375,33.6 r0 top
C306 "1uF/10V" 0201_0.25D -32.225,46.075 r270 top
C307 "1uF/10V" 0201_0.25D -16.75,46.2 r270 top
C308 "1uF/10V" 0201_0.25D -16,46.2 r270 top
C309 "1uF/10V" 0201_0.25D -24.125,46.075 r270 top
C400 "2.2uF/10V" 0402C_0.4D-NB -5.275,36.525 r180 bottom
C401 "0.1uF/10V" 0201_0.25D -5.325,37.25 r0 bottom
C402 "NC" 0201_0.25D -9.45,35.025 r90 bottom
C403 "NC" 0201_0.25D -8.675,35.025 r90 bottom
C404 "0.1uF/10V" 0201_0.25D -5.325,37.925 r0 bottom
C405 "NC" 0201_0.25D -24,34.45 r0 top
C406 "0.47uF" 0201_0.25D -5.329,16.376 r180 bottom
C407 "0.47uF" 0201_0.25D -5.336,17.072 r180 bottom
C408 "NC" 0201_0.25D -7.125,35.025 r90 bottom
C409 "NC" 0201_0.25D -5.325,38.875 r180 bottom
C410 "1uF/10V" 0201_0.25D -10.026,16.749 r270 bottom
C411 "10uF/10V" 0402C_0.4D -9.525,10.075 r180 top
C412 "0.1uF/10V" 0201_0.25D -9.501,9.125 r0 top
C413 "0.1uF/10V" 0201_0.25D -10.85,36.675 r180 bottom
C414 "2.2uF/10V" 0402C_0.4D-NB -8.05,41.175 r90 bottom
C415 "2.2uF/10V" 0402C_0.4D-NB -8.85,41.175 r90 bottom
C416 "1uF/6.3V" 0201_0.25D -9.566,40.639 r270 bottom
C417 "1uF/6.3V" 0201_0.25D -10.85,39.225 r0 bottom
C418 "1uF/6.3V" 0201_0.25D -10.85,38.6 r0 bottom
C419 "2.2uF/10V" 0402C_0.4D-NB -10.875,35.95 r0 bottom
C420 "1uF/6.3V" 0201_0.25D -7.946,46.231 r90 bottom
C421 "15pF" 0201C_0.2D(NB) -6.875,42.275 r180 bottom
C422 "0.1uF/10V" 0201C_0.2D(NB) -8.346,47.081 r180 bottom
C423 "0.1uF/6.3V" 0201_0.25D -25.3,27.875 r270 bottom
CON100 "nano-SIM Connector" SIM-MUP-C7801 -37.2,26.2 r90 bottom locked
CON101 "USB-TYPE C-12P" "TYPEC _6PIN板" -41.2,25 r270 top locked
CON102 "11-0440103-330" SMD-1.5-3P -41,11.075 r90 bottom
CON200 "HW0520010-202R-001" FPC0.5E-20P -27.385,6.088 r0 bottom locked
CON201 "FPC-24" 0.5S-3S-24PWB -22.5,45.676 r180 bottom locked
CON400 "11-0672002-33C" SMD-1.5-2P -9.825,4.025 r180 bottom
CON401 "11-0702002-331" SMD-1.25-2P -8.35,40.475 r180 top locked
D100 "TVS" DFN1006-NP -28.7,28.3 r270 bottom
D101 "DIODE-2TVS-2" DFN1006-NP -36.65,26.375 r90 top
D102 "DIODE-2TVS-2" DFN1006-NP -36.65,24.65 r270 top
D103 "DIODE-TVS" UDFN2(1610) -36.175,22.15 r0 top
D104 "DIODE" SOD-123-FL -36.742,17.698 r90 top
D105 "DIODE-TVS" UDFN2(1610) -34.702,18.158 r90 top
D200 "TVS" DFN1006-NP -27.056,42.051 r180 bottom
D300 "TVS" DFN1006-NP -16.625,38.975 r270 top
D301 "TVS" DFN1006-NP -40.55,40.725 r0 top
D302 "TVS" DFN1006-NP -40.55,13.45 r0 top
D303 "TVS" DFN1006-NP -4.55,12.725 r180 top
D304 "TVS" DFN1006-NP -4.5,22.725 r180 top
D305 "TVS" DFN1006-NP -4.475,32.7 r180 top
D400 "WS6183KF" DFN1006-NP -6.679,44.068 r0 bottom
H300 "M3*6.5*5" Toolinghole -3,47 r0 top
H301 "M3*6.5*5" Toolinghole -42,47 r0 top locked
H302 "M3*6.5*5" Toolinghole -3,3 r0 top locked
H303 "M3*6.5*5" Toolinghole -42,3 r0 top locked
K300 "1414000735" TS3443-0253B -20.3,40.35 r90 top
K301 "BUTTON-2-2" SW-7.8X3.5-4P-HOLE-S -43.25,38.65 r270 top locked
K302 "BUTTON-2-2" SW-7.8X3.5-4P-HOLE-S -43.25,11.35 r270 top locked
K303 "BUTTON-2-2" SW-7.8X3.5-4P-HOLE-S -1.687,14.875 r90 top locked
K304 "BUTTON-2-2" SW-7.8X3.5-4P-HOLE-S -1.687,24.85 r90 top locked
K305 "BUTTON-2-2" SW-7.8X3.5-4P-HOLE-S -1.687,34.825 r90 top locked
LED300 "GH" D0402 -41.825,17.775 r0 top
LED301 "R6" D0402 -41.825,16.65 r0 top
LED302 "XL-1615RGBC-WS2812B" D1615RGBC -31.625,47.85 r180 top
LED303 "XL-1615RGBC-WS2812B" D1615RGBC -23.5,47.85 r180 top
LED304 "XL-1615RGBC-WS2812B" D1615RGBC -15.375,47.825 r180 top
Oil300 "Oil" "White oil-6X6" -9.675,4.875 r0 top
P200 "SPI 4-M" "SIP 2.54_4_S" -8.25,21.32 r180 top
Q100 "WM02N20F" DFN1006-3G -31.475,30.85 r180 top
Q101 "DTC143ZM" SOT-723-3A -26.15,11.775 r0 top
Q102 "P-MOS-D1" SOT-23-3G -34.85,13.75 r90 bottom
Q103 "YJA3139KB" DFN1006-3G -27.8,10.025 r90 top
Q300 "P-MOS-D" DFN1006-3G -14.25,42.05 r270 bottom
Q301 "N-MOS-D" SOT-723-3G -14,39.7 r270 bottom
R100 "NC" 0201_0.25D -27.6,28.625 r180 bottom
R101 "NC" 0201_0.25D -27.279,19.995 r0 bottom
R102 "0R" 0201_0.25D -39.75,7.9 r0 top
R103 "100K" 0201_0.25D -39.75,6.6 r180 top
R104 "33R" 0201_0.25D -24.875,34.625 r90 top
R105 "33R" 0201_0.25D -22.675,34.625 r90 top
R106 "33R" 0201_0.25D -21.575,34.625 r90 top
R107 "33R" 0201_0.25D -17.148,34.625 r90 top
R108 "5.1K" 0201_0.25D -36.65,27.575 r0 top
R109 "5.1K" 0201_0.25D -36.55,23.275 r0 top
R110 "1.2K/1%" 0201_0.25D -30.5,7.861 r0 top
R111 "5.6K/1%" 0201_0.25D -30.5,5.925 r180 top
R112 "110K/1%" 0201_0.25D -30.5,6.6 r0 top
R113 "100K" 0201_0.25D -32.867,30.527 r180 top
R114 "33R" 0201_0.25D -20.748,21.711 r180 bottom
R115 "33R" 0201_0.25D -17.825,7.75 r90 bottom
R116 "33R" 0201_0.25D -18.475,7.75 r90 bottom
R117 "33R" 0201_0.25D -20.375,7.75 r90 bottom
R118 "1K" 0201_0.25D -32.867,31.175 r180 top
R119 "33R" 0201_0.25D -14.689,23.275 r270 bottom
R120 "NC" 0201_0.25D -22.86,7.812 r270 bottom
R121 "10K" 0201_0.25D -28.15,11.5 r270 top
R122 "1K" 0201_0.25D -27.475,11.5 r90 top
R123 "33R" 0201_0.25D -21.082,29.06 r180 bottom
R124 "470K" 0402R_0.4D -36.205,20.828 r180 top
R125 "47K/1%" 0201_0.25D -26.725,9.625 r180 top
R126 "47K/1%" 0201_0.25D -25.152,9.905 r270 top
R127 "4.7K" 0201_0.25D -18.425,38.175 r180 bottom
R128 "4.7K" 0201_0.25D -20.206,15.62 r180 bottom
R129 "47K" 0201_0.25D -20,38.45 r270 bottom
R130 "47K" 0201_0.25D -21.818,13.941 r90 bottom
R131 "NC" 0201_0.25D -19.344,38.45 r270 bottom
R132 "NC" 0201_0.25D -22.468,13.941 r90 bottom
R133 "33R" 0201_0.25D -9.875,31.325 r0 top
R134 "33R" 0201_0.25D -9.881,31.955 r0 top
R200 "NC" 0201_0.25D -28.306,42.426 r270 bottom
R201 "NC" 0201_0.25D -25.806,42.626 r270 bottom
R202 "33R" 0201_0.25D -20.206,42.876 r90 bottom
R203 "33R" 0201_0.25D -19.281,42.876 r90 bottom
R204 "33R" 0201_0.25D -18.281,42.876 r90 bottom
R300 "0R" 0201_0.25D -33.125,48.05 r270 top
R301 "1K" 0201C_0.2D(NB) -39.123,18.301 r0 top
R302 "2K" 0201C_0.2D(NB) -40.133,18.312 r0 top
R303 "470R" 0201C_0.2D(NB) -40.15,17.775 r0 top
R304 "1K" 0201C_0.2D(NB) -40.15,16.65 r0 top
R305 "100K" 0201_0.25D -14.25,40.875 r0 bottom
R306 "10K" 0201_0.25D -14,38.475 r0 bottom
R400 "0R" 0201_0.25D -12.422,16.534 r0 bottom
R401 "NC" 0201_0.25D -11.25,16.534 r0 bottom
R402 "100K" 0201_0.25D -12.917,14.815 r90 bottom
R403 "4.7K" 0201_0.25D -7.225,40.875 r90 bottom
R404 "4.7K" 0201_0.25D -5.325,39.525 r0 bottom
R405 "NC" 0201_0.25D -6.158,35.23 r180 bottom
R406 "33R" 0201_0.25D -7.8,35.025 r90 bottom
R407 "69.8K/1%" 0201_0.25D -6.467,16.377 r180 bottom
R408 "69.8K/1%" 0201_0.25D -6.475,17.075 r180 bottom
R409 "10K" 0201_0.25D -6.575,40.875 r90 bottom
R410 "0R" 0201_0.25D -10.85,37.95 r0 bottom
R411 "0R" 0201_0.25D -10.85,37.325 r0 bottom
R412 "0R" 0201C_0.2D(NB) -7.85,42.275 r180 bottom
R413 "0R" 0201C_0.2D(NB) -9.025,42.25 r0 bottom
R414 "220R" 0201_0.25D -8.596,46.231 r90 bottom
R415 "2.2K" 0201_0.25D -7.825,42.85 r0 bottom
R416 "2.2K" 0201_0.25D -9.025,42.825 r0 bottom
R417 "33R" 0201_0.25D -16.8,26.875 r270 bottom
R418 "4.7K" 0201_0.25D -16.8,25.575 r270 bottom
R419 "4.7K" 0201_0.25D -25.3,26.725 r90 bottom
TP100 "M_RX" test#1 -12.508,23.767 r180 bottom
TP101 "M_TX" TEST -12.525,25.425 r90 bottom
TP102 "D_TX" test#1 -30.875,25.2 r180 top
TP103 "D_RX" TEST -30.875,26.875 r0 top
TP104 "NTC" test#2 -32.225,6.753 r90 bottom
TP105 "PWM0" test#1 -14.45,20.05 r90 bottom
TP106 "PWM1" test#1 -14.425,21.8 r90 bottom
TP107 "VBAT_Li" test#1 -24.875,11.2 r0 bottom
TP108 "VBUS" test#1 -30.553,10.209 r0 bottom
TP109 "USB_DN" test#1 -16.95,30.3 r180 bottom
TP110 "USB_DP" test#1 -15.477,30.3 r180 bottom
TP111 "VBAT" test#1 -23.641,13.51 r180 bottom
TP112 "CAM_VDD" test#3 -26.679,40.6 r90 top
TP113 "3V3" test#1 -16.902,10.43 r180 bottom
TP300 "BOOT" test#1 -17.688,39.626 r90 bottom
TP301 "PWRKEY" test#1 -41.043,38.548 r180 bottom
TP302 "RESET" test#1 -40.9,17.15 r180 bottom
TP303 "KEY_USER0" test#1 -3.374,11.807 r0 bottom
TP304 "KEY_USER1" test#1 -3.374,21.805 r0 bottom
TP305 "KEY_USER2" test#1 -3.374,31.83 r0 bottom
TP306 "VDD_EXT" test#1 -19.868,34.9 r90 bottom
TP307 "GND" test#1 -36.175,33.825 r90 bottom
TP308 "GND" test#1 -5.475,9.7 r90 bottom
U100 "NSQA6V8AW5T2G" SOT-323-5 -28.2,22.375 r270 bottom
U101 "NC" DFN8(1.27)-6X5 -37.6,25.045 r180 bottom
U102 "NT26F6D0" "NT26-FCN B" -20.475,25.325 r90 top locked
U103 "CL4056D" SOP-8(1.27)-GND#1 -35.225,8.493 r90 top
U104 "SGM2036-XYN5G/TR" SOT-23-5P -22.6,39.125 r0 bottom
U105 "SGM2036-XYN5G/TR" SOT-23-5P -19.143,13.241 r180 bottom
U400 "ES8311" QFN20(0.4)-3X3 -8.2,37.9 r180 bottom locked
U401 "CST8302A" SOP-8(1.27)-GND#2 -9.535,12.275 r0 bottom
U402 "P25Q32SH-SSH-IR" SOP-8(1.27) -21.06,25.78 r270 bottom
U403 "MSM381ACT001" 麦克风MSM381ACT001 -8.5,47.3 r180 top

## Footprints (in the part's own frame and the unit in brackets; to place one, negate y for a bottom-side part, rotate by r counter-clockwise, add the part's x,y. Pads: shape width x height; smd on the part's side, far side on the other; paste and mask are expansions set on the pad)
0.5S-3S-24PWB [mm]
  rrect40% 2x3 smd mask+0.075: 0(-7.15,1.175) 0(7.15,1.175)
  rect 0.28x1.3 smd mask+0.051: 1(5.75,-1.175)
  oval 0.28x1.3 smd mask+0.051: 2(5.25,-1.175) 3(4.75,-1.175) 4(4.25,-1.175) 5(3.75,-1.175) 6(3.25,-1.175) 7(2.75,-1.175) 8(2.25,-1.175) 9(1.75,-1.175) 10(1.25,-1.175) 11(0.75,-1.175) 12(0.25,-1.175) 13(-0.25,-1.175) 14(-0.75,-1.175) 15(-1.25,-1.175) 16(-1.75,-1.175) 17(-2.25,-1.175) 18(-2.75,-1.175) 19(-3.25,-1.175) 20(-3.75,-1.175) 21(-4.25,-1.175) 22(-4.75,-1.175) 23(-5.25,-1.175) 24(-5.75,-1.175)
  silkscreen extent -8.93,0.06 8.89,4.24, body extent -9.15,-0.63 9.15,4.08, height 2.05
0201_0.25D [mm]
  rect 0.3x0.3 smd mask+0.051: 1(-0.275,0) 2(0.275,0)
  body extent -0.3,-0.15 0.3,0.15, height 0.28
0201C_0.2D(NB) [mm]
  rrect17% 0.3x0.3 smd mask+0.05: 1(-0.25,0) 2(0.25,0)
  body extent -0.3,-0.15 0.3,0.15, height 0.3
0402C_0.4D [mm]
  rect 0.525x0.6 smd: 1(-0.463,0) 2(0.463,0)
  silkscreen extent -0.96,-0.5 0.96,0.5, body extent -0.5,-0.25 0.5,0.25, height 0.48
0402C_0.4D-NB [mm]
  rrect44% 0.45x0.5 smd mask+0.05: 1(-0.4,0) 2(0.4,0)
  silkscreen extent -0.7,-0.3 0.7,0.3, body extent -0.5,-0.25 0.5,0.25, height 0.5
0402R_0.4D [mm]
  rect 0.525x0.6 smd: 1(-0.463,0) 2(0.463,0)
  silkscreen extent -0.96,-0.5 0.96,0.5, body extent -0.5,-0.25 0.5,0.25, height 0.36
6032-TC [mm]
  rect 2.6x2.8 smd: 1(2.5,0) 2(-2.5,0)
  silkscreen extent -4.09,-1.95 4.7,1.95, body extent -3.06,-1.61 3.13,1.6, height 2.67
"Bad Mark" [mm]
  round 2 on Top Solder: 2(0,0)
  round 2 on Bottom Solder: 2(0,0)
  Top Layer pour cut-out: -1.051,0 -0.971,-0.402 -0.743,-0.743 -0.402,-0.971 0,-1.051 0,-1.051 0.402,-0.971 0.743,-0.743 0.971,-0.402 1.051,0 1.051,0 0.971,0.402 0.743,0.743 0.402,0.971 0,1.051 0,1.051 -0.402,0.971 -0.743,0.743 -0.971,0.402 -1.051,0
  Top Layer region: -0.25,0.5 0.25,0.5 0.25,-0.5 -0.25,-0.5
  Top Layer region: -0.5,-0.25 -0.5,0.25 0.5,0.25 0.5,-0.25
  Bottom Layer region: 0.5,-0.25 0.5,0.25 -0.5,0.25 -0.5,-0.25
  Bottom Layer region: 0.25,0.5 -0.25,0.5 -0.25,-0.5 0.25,-0.5
  Bottom Layer pour cut-out: 1.051,0 0.971,-0.402 0.743,-0.743 0.402,-0.971 0,-1.051 0,-1.051 -0.402,-0.971 -0.743,-0.743 -0.971,-0.402 -1.051,0 -1.051,0 -0.971,0.402 -0.743,0.743 -0.402,0.971 0,1.051 0,1.051 0.402,0.971 0.743,0.743 0.971,0.402 1.051,0
D0402 [mm]
  rect 0.6x0.7 smd: A(0.55,0) K(-0.55,0)
  silkscreen extent -1.1,-0.5 1.01,0.5, body extent -0.55,-0.33 0.55,0.33, height 0.56
D1615RGBC [mm]
  rect 0.45x0.65 smd paste+0 mask+0.05: 1(-0.625,-0.475) 2(0.625,-0.475) 3(0.625,0.475) 4(-0.625,0.475)
  silkscreen extent -0.99,-1.29 0.97,0.94, body extent -0.75,-0.8 0.75,0.8, height 0.6
DFN8(1.27)-6X5 [mm]
  rect 1.3x1.8 smd: 0(-0.889,-1.143) 0(-0.889,1.143) 0(0.889,-1.143) 0(0.889,1.143)
  rect 1.1x0.4 smd: 1(-2.8,1.905) 2(-2.8,0.635) 3(-2.8,-0.635) 4(-2.8,-1.905) 5(2.8,-1.905) 6(2.8,-0.635) 7(2.8,0.635) 8(2.8,1.905)
  round 0.3 on Mech13 mask+0: ""(-2.8,1.905)
  rect 0.6x0.4 on Mech1 mask+0: ""(-2.7,-1.905) ""(-2.7,-0.635) ""(-2.7,0.635) ""(-2.7,1.905) ""(2.7,-1.905) ""(2.7,-0.635) ""(2.7,0.635) ""(2.7,1.905)
  round 0.3 on Mech1 mask+0: ""(0,0) ""(0,0)
  rect 3.4x4.2 on Mech1 mask+0: ""(0,0)
  silkscreen extent -3,-2.54 3,2.54
DFN1006-3G [mm]
  rect 0.4x0.6 smd mask+0.05: D(-0.4,0)
  rect 0.4x0.2 smd mask+0.05: G(0.4,-0.175) S(0.4,0.175)
  silkscreen extent -0.7,-0.4 0.95,0.4, body extent -0.5,-0.3 0.5,0.3, height 0.5
DFN1006-NP [mm]
  rect 0.4x0.7 smd mask+0.051: A(0.35,0) K(-0.35,0)
  rect 0.25x0.5 on Mech1: ""(-0.325,0) ""(0.325,0)
  silkscreen extent -0.85,-0.5 0.85,0.5, body extent -0.5,-0.3 0.5,0.3, height 0.5
FPC0.5E-20P [mm]
  rect 1.8x2.2 smd mask+0.075: 0(-2.05,2.25) 0(11.55,2.25)
  rect 0.28x1.4 smd mask+0.051: 1(9.5,0)
  oval 0.28x1.4 smd mask+0.051: 2(9,0) 3(8.5,0) 4(8,0) 5(7.5,0) 6(7,0) 7(6.5,0) 8(6,0) 9(5.5,0) 10(5,0) 11(4.5,0) 12(4,0) 13(3.5,0) 14(3,0) 15(2.5,0) 16(2,0) 17(1.5,0) 18(1,0) 19(0.5,0) 20(0,0)
  silkscreen extent -2.75,1.14 12.25,6.05, body extent -2.4,0.44 11.9,6.04, height 2
IPX_U.FL-R-SMT-1 [mm]
  rrect50% 1.05x1 smd: 1(-1.575,0)
  oct 2x1.2 smd: 2(0,-1.6) 3(0,1.6)
  Top Layer pour cut-out: 1.1,1.5 1.1,-1.5 -1.075,-1.5 -1.075,1.5
  silkscreen extent -1.5,-1.5 2.5,1.5, body extent -1.55,-1.5 1.55,1.5, height 1.25
"NT26-FCN B" [mm]
  rrect20% 1.3x0.6 smd mask+0.076: 1(-7.15,6.6) 2(-7.15,5.5) 3(-7.15,4.4) 4(-7.15,3.3) 5(-7.15,2.2) 6(-7.15,1.1) 7(-7.15,0) 8(-7.15,-1.1) 9(-7.15,-2.2) 10(-7.15,-3.3) 11(-7.15,-4.4) 12(-7.15,-5.5) 13(-7.15,-6.6) 23(7.15,-6.6) 24(7.15,-5.5) 25(7.15,-4.4) 26(7.15,-3.3) 27(7.15,-2.2) 28(7.15,-1.1) 29(7.15,0) 30(7.15,1.1) 31(7.15,2.2) 32(7.15,3.3) 33(7.15,4.4) 34(7.15,5.5) 35(7.15,6.6)
  rrect20% 0.6x1.3 smd mask+0.076: 14(-4.4,-8.1) 15(-3.3,-8.1) 16(-2.2,-8.1) 17(-1.1,-8.1) 18(0,-8.1) 19(1.1,-8.1) 20(2.2,-8.1) 21(3.3,-8.1) 22(4.4,-8.1) 36(4.4,8.1) 37(3.3,8.1) 38(2.2,8.1) 39(1.1,8.1) 40(0,8.1) 41(-1.1,8.1) 42(-2.2,8.1) 43(-3.3,8.1) 44(-4.4,8.1) 95(-5.5,-8.1) 96(5.5,-8.1) 97(5.5,8.1) 98(-5.5,8.1)
  rrect30% 1x0.7 smd mask+0.064: 45(-5,4.8) 46(-5,3.6) 47(-5,2.4) 48(-5,1.2) 49(-5,0) 50(-5,-1.2) 51(-5,-2.4) 52(-5,-3.6) 53(-5,-4.8) 59(5,-4.8) 60(5,-3.6) 61(5,-2.4) 62(5,-1.2) 63(5,0) 64(5,1.2) 65(5,2.4) 66(5,3.6) 67(5,4.8) 73(-3.2,4.2) 74(-3.2,3) 75(-3.2,1.8) 76(-3.2,0.6) 77(-3.2,-0.6) 78(-3.2,-1.8) 79(-3.2,-3) 80(-3.2,-4.2) 81(3.2,-4.2) 82(3.2,-3) 83(3.2,-1.8) 84(3.2,-0.6) 85(3.2,0.6) 86(3.2,1.8) 87(3.2,3) 88(3.2,4.2) 99(-5,6) 100(-5,-6) 103(5,-6) 104(5,6)
  rrect30% 0.7x1 smd mask+0.064: 54(-2.4,-5.95) 55(-1.2,-5.95) 56(0,-5.95) 57(1.2,-5.95) 58(2.4,-5.95) 68(2.4,5.95) 69(1.2,5.95) 70(0,5.95) 71(-1.2,5.95) 72(-2.4,5.95) 101(-3.6,-5.95) 102(3.6,-5.95) 105(3.6,5.95) 106(-3.6,5.95) 107(-1.2,-4.2) 108(0,-4.2) 109(1.2,-4.2)
  rrect20% 1.3x1.3 smd mask+0.064: 89(-0.9,1.8) 90(-0.9,0) 91(-0.9,-1.8) 92(0.9,-1.8) 93(0.9,0) 94(0.9,1.8)
  silkscreen extent -8.53,-9 8.05,9
QFN20(0.4)-3X3 [mm]
  rect 1.5x1.5 smd mask+0.051: 0(0,0)
  rect 0.8x0.2 smd mask+0.051: 1(-1.5,0.8)
  oval 0.8x0.2 smd mask+0.051: 2(-1.5,0.4) 3(-1.5,0) 4(-1.5,-0.4) 5(-1.5,-0.8) 11(1.5,-0.8) 12(1.5,-0.4) 13(1.5,0) 14(1.5,0.4) 15(1.5,0.8)
  oval 0.2x0.8 smd mask+0.051: 6(-0.8,-1.5) 7(-0.4,-1.5) 8(0,-1.5) 9(0.4,-1.5) 10(0.8,-1.5) 16(0.8,1.5) 17(0.4,1.5) 18(0,1.5) 19(-0.4,1.5) 20(-0.8,1.5)
  round 0.4 on Mech13: ""(-1.5,0.8)
  silkscreen extent -2.3,-1.65 1.65,1.65
SIM-MUP-C7801 [mm]
  rect 0.58x2.1 smd: 0(-6.5,-6.742) 0(-6.5,5.258) 0(6.5,-6.742) 0(6.5,5.258)
  rect 1.8x2.8 on Mech1: 0(-3.82,-5.743) 0(-1.28,-5.743) 0(1.26,-5.743)
  rect 1.4x2.95 on Mech1: 0(-3.82,0.233) 0(-1.28,0.233) 0(1.26,0.233)
  rect 1.4x2.3 on Mech1: 0(1.26,4.257)
  rect 0.7x1.13 smd: 1(0.25,6.743) 2(-2.29,6.743) 5(1.52,6.743) 6(-1.02,6.743) 7(-3.56,6.743)
  rect 0.75x1.13 smd: 3(-4.83,6.743)
  rect 0.65x1.13 smd: CD(2.47,6.743)
  silkscreen extent -6.1,-11.59 6.1,6.01
"SIP 2.54_4_S" [mm]
  round 1.7 hole 1.02: 1(0,0) 2(0,-2.54) 3(0,-5.08) 4(0,-7.62)
  silkscreen extent -1.27,-8.89 1.27,1.27, body extent -1.27,-8.89 1.27,1.27, height 10.3
SMD-1.5-2P [mm]
  rect 1.5x2.3 smd paste+0: 0(-2.8,-2.425) 0(2.8,-2.425)
  rect 0.7x2.9 smd paste+0: 1(-0.75,2.125) 2(0.75,2.125)
  silkscreen extent -3.85,-3.85 3.85,3.9, body extent -3.02,-3.95 2.98,2.55, height 3.73
SMD-1.5-3P [mm]
  rect 1.5x2.3 smd paste+0: 0(-3.55,-2.425) 0(3.55,-2.425)
  rect 0.7x2.9 smd paste+0: 1(-1.5,2.125) 2(0,2.125) 3(1.5,2.125)
  silkscreen extent -4.6,-3.85 4.6,3.9, body extent -3.75,-3.95 3.75,2.55, height 3.73
SMD-1.25-2P [mm]
  rect 2.1x3.1 smd: 0(-3.175,-1.45) 0(3.175,-1.45)
  rect 0.8x1.7 smd: 1(-0.625,1.45) 2(0.625,1.45)
  silkscreen extent -4.46,-3.55 4.48,2.59, body extent -2.2,-3.55 2.19,0.65, height 3.45
SOD-123-FL [mm] "焊盘宽度0.9-1.1"
  rect 1.2x1.2 smd: A(1.7,0) K(-1.7,0)
  silkscreen extent -1.57,-1 1.5,1, body extent -1.8,-0.83 1.8,0.82, height 0.95
SOP-8(1.27) [mm] "5*6"
  rect 0.55x1.7 smd: 1(-1.905,-2.8)
  oval 0.55x1.7 smd: 2(-0.635,-2.8) 3(0.635,-2.8) 4(1.905,-2.8) 5(1.905,2.8) 6(0.635,2.8) 7(-0.635,2.8) 8(-1.905,2.8)
  round 0.5 on Mech13 mask+0.3: ""(-1.92,-2.56)
  silkscreen extent -2.9,-2.88 2.54,1.8, body extent -2.53,-3.13 2.53,3.13, height 1.76
SOP-8(1.27)-GND#1 [mm] "5*6"
  rect 3.5x2.6 smd: 0(0.01,0)
  rect 0.55x1.7 smd: 1(-1.905,-2.8)
  oval 0.55x1.7 smd: 2(-0.635,-2.8) 3(0.635,-2.8) 4(1.905,-2.8) 5(1.905,2.8) 6(0.635,2.8) 7(-0.635,2.8) 8(-1.905,2.8)
  round 0.5 on Mech15 mask+0.3: ""(-1.92,-2.553)
  silkscreen extent -2.9,-2.88 2.54,1.8, body extent -2.52,-3.13 2.54,3.13, height 1.76
SOP-8(1.27)-GND#2 [mm] "5*6"
  rect 3.5x2.6 smd: 0(0.01,0)
  rect 0.55x1.7 smd: 1(-1.905,-2.8)
  oval 0.55x1.7 smd: 2(-0.635,-2.8) 3(0.635,-2.8) 4(1.905,-2.8) 5(1.905,2.8) 6(0.635,2.8) 7(-0.635,2.8) 8(-1.905,2.8)
  round 0.5 on Mech13 mask+0.3: ""(-1.92,-2.553)
  silkscreen extent -2.9,-2.88 2.54,1.8, body extent -2.52,-3.13 2.54,3.13, height 1.76
SOT-23-3G [mm]
  rect 1x0.8 smd: D(-1.05,0) G(1.05,-0.95) S(1.05,0.95)
  rect 0.55x0.5 on Mech1: ""(-1.025,0) ""(1.025,-0.95) ""(1.025,0.95)
  silkscreen extent -1.19,-1.77 1.25,1.77, body extent -1.41,-1.45 1.41,1.45, height 1.22
SOT-23-5P [mm]
  rect 1.1x0.508 smd: 1(1.35,-0.95) 2(1.35,0) 3(1.35,0.95) 4(-1.35,0.95) 5(-1.35,-0.95)
  silkscreen extent -1.3,-1.81 2.06,1.79, body extent -1.5,-1.5 1.5,1.5, height 1.3
SOT-323-5 [mm]
  rect 0.8x0.4 smd mask+0.051: 1(1,-0.65) 2(1,0) 3(1,0.65) 4(-1,0.65) 5(-1,-0.65)
  silkscreen extent -0.6,-1.1 1.85,1.1, body extent -1.2,-1.1 1.2,1.1, height 1.1
SOT-723-3A [mm]
  rect 0.4x0.4 smd: B(0.5,-0.4) C(-0.5,0) E(0.5,0.4)
  silkscreen extent -0.52,-0.65 0.07,0.65, body extent -0.5,-0.63 0.55,0.63, height 0.45
SOT-723-3G [mm]
  rect 0.4x0.4 smd: D(-0.5,0) G(0.5,-0.4) S(0.5,0.4)
  silkscreen extent -0.52,-0.65 0.07,0.65, body extent -0.5,-0.63 0.55,0.62, height 0.45
SW-7.8X3.5-4P-HOLE-S [mm]
  rect 1.45x1 smd mask+0.05: 1(-3.375,-0.887) 2(3.375,-0.887)
  rect 0.9x1.3 smd mask+0.05: 3(-2.1,0.888) 4(2.1,0.888)
  Keep-Out Layer circle w0.149: c1.15,0 r0.45
  Keep-Out Layer circle w0.149: c-1.15,0 r0.45
  silkscreen extent -3.9,-2.4 3.9,1.1, body extent -3.9,-2.4 3.9,1.4, height 3.47
test#1 [mm]
  round 1 smd paste-10: 1(0,0)
test#2 [mm]
  round 1.2 smd paste-10: 1(0,0)
test#3 [mm]
  round 1 smd far side paste-10: 1(0,0)
TEST [mm]
  round 1 smd paste-10: 1(0,0)
Toolinghole [mm]
  round 2.5 hole 2.5 unplated: 1(0,0)
  silkscreen extent -1.6,-1.6 1.6,1.6
TS3443-0253B [mm]
  rect 0.7x1.3 smd: 1(-1.075,-2.2) 2(-1.075,2.2) 3(1.075,-2.2) 4(1.075,2.2)
  silkscreen extent -1.9,-2.3 1.9,2.3, body extent -1.7,-2.2 1.7,2.2, height 2.5
"TYPEC _6PIN板" [mm]
  rect 2x2 smd mask+0.064: 0(-4.77,1.488) 0(-4.77,-2.412) 0(4.77,1.488) 0(4.77,-2.412)
  rect 0.6x1.4 smd mask+0.051: A1B12(-3.2,2.413) A4B9(-2.4,2.413) B1A12(3.2,2.413) B4A9(2.4,2.413)
  rect 0.3x1.4 smd mask+0.051: A5(-1.25,2.413) A6(-0.25,2.413) A7(0.25,2.413) A8(1.25,2.413) B5(1.75,2.413) B6(0.75,2.413) B7(-0.75,2.413) B8(-1.75,2.413)
  round 0.65 hole 0.65 unplated mask+0.102: ""(-2.89,0.968) ""(2.89,0.968)
  silkscreen extent -4.67,-5.09 4.67,3.3, body extent -5.72,-5.2 5.72,2.55, height 3.23
UDFN2(1610) [mm]
  rect 0.58x1 smd mask+0.076: A(0.56,0) K(-0.56,0)
  rect 0.4x0.88 on Mech1: ""(-0.55,0) ""(0.55,0)
  silkscreen extent -1.15,-0.7 1.05,0.7, body extent -0.8,-0.5 0.8,0.5, height 0.59
"White oil-6X6" [mm] "二维码白油块"
  round 0.3 on Mech1: 29(0,0)
  silkscreen extent -3,-3 3,3
麦克风MSM381ACT001 [mm]
  rect 0.7x0.7 smd: 1(0.55,1) 2(0.55,-1) 3(-0.55,-1) 4(-0.55,1)
  silkscreen extent -1.06,-1.53 1.12,1.55, body extent -0.93,-1.38 0.93,1.37, height 1.05

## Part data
ANT100: library part 1416000325, "DC-6GHz"
C100 C109 C112 C113 C114 C117 C118 C200 C201 C202 C212 C213 C300 C301 C302 C303 C304 C305 C306 C307 C308 C309 C401 C404 C413 C416 C417 C418 C420: library part 1405002136, "1uF/6.3V/20%/X5R"
C101 C104 C412 C422 C423: library part 1405001272, "0.1uF/10V/10%/X5R"
C102: library part 1405000173, "220uF/6.3V/10%/1.2Ω"
C103 C106 C111 C411: library part 1405001308, "10uF/10V/20%/X5R"
C105 C107 C108 C110 C203 C204 C205 C206 C207 C208 C209 C210 C211: library part 1405002411, "33pF/50V/5%/C0G"
C115 C116: library part 1405001481, "10nF/16V/10%/X7R"
C400 C414 C415 C419: library part 1405001497, "2.2uF/6.3V/20%/X5R"
C402 C403 C405 C408 C409: library part 1405000291, "33pF/50V/5%/C0G"
C406 C407: library part 1405005412, "22nF/10V/10%/X5R"
C410: library part 1405005056, "1uF/10V/20%/X5R"
C421: library part 1405001343, "15pF/50V/5%/C0G"
CON100: library part 1416003211, "Push-Push NANO-SIM Card Connector"
CON101: library part 1416003448, "USB Type-C"
CON102: library part 1416001211, "1.25mm/3PIN"
CON200: library part 1416002856, "0.50mm/20PIN"
CON201: library part 1416000423, "0.50mm/24PIN"
CON400: library part 1416003013, "1.25mm/2PIN"
CON401: library part 1416002711, "1.25mm/2PIN"
D100 D200 D300 D301 D302 D303 D304 D305 D400: library part 1409004149, "1通道"
D101 D102: library part 1409004148, "1通道"
D103: library part 1409004319, "1通道"
D104: library part 1409001001, "1000V/1A"
D105: library part 1409003028, "1通道/4.5V/12V/2160W/600pF"
H300 H301 H302 H303: library part 1602002834, "M3*6.5*5/铜"
K300: library part 1416003591, "6*6*7.3"
K301 K302 K303 K304 K305: library part 1414000145, "7.8*3.5*3.5"
LED300: library part 1409003070, "绿/25mA/112-225mcd"
LED301: library part 1409000384, "红/25mA/40mcd"
LED302 LED303 LED304: library part WS2812B
P200: library part 1416000794, "2.54mm/1*4PIN/直"
Q100: library part N-MOS
Q101: library part 1412002731, "NPN/100mA/50V/100mW"
Q102: library part 1412000290, "PMOS/20V/4.7A"
Q103: library part 1412003096, "PMOS/-20V/0.65A"
Q300: library part 1412003017, "PMOS/20V/0.65A"
Q301: library part 1412003327, "NMOS/20V/0.5A"
R100 R101 R103 R108 R109 R118 R121 R122 R200 R201 R300 R301 R302 R303 R304: library part 1408005605, "5.1KΩ/1%"
R102 R110 R111 R112 R306: library part 1408001444, "10KΩ/5%"
R104 R105 R106 R107 R114 R115 R116 R117 R119 R120 R123 R133 R134 R202 R203 R204 R403 R404 R405 R406 R409 R414 R415 R416 R417 R418 R419: library part 1408001443, "33Ω/5%"
R113: library part 1408005604, "10K/5%"
R124: library part 1408000869, "1M/5%"
R125 R126 R129 R130 R400 R401 R402 R407 R408: library part 1408001835, "47KΩ/1%"
R127 R128: library part 1408001558, "4.7KΩ/5%"
R131 R132 R305: library part 1408005685, "100KΩ/5%"
R410 R411 R412 R413: library part 1408001445, "1KΩ/5%"
TP100 TP101 TP102 TP103 TP105 TP106: library part TP
TP104 TP107 TP108 TP109 TP110 TP111 TP112 TP113 TP300 TP301 TP302 TP303 TP304 TP305 TP306 TP307 TP308: library part MARK
U100: library part 1409000217, "双向/7.14V/600W"
U101: library part 180006-03G
U103: library part CL4056
U104: library part 1407001782, "2.8V/300mA/1.6-5.5V"
U105: library part 1407000926, "3.3V/300mA/1.6-5.5V"
U400: "QFN20-3*3mm"
U402: library part P25Q64SLA-SUH-IR
U403: library part SI-MIC, "1406000322"

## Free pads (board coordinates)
  round 1 on Mech1: 0(-30.625,47.85) 0(-22.5,47.85) 0(-14.375,47.85)

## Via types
v1: diameter 0.4, hole 0.2, Top Layer to Bottom Layer, tented both sides, 541 vias
v2: diameter 0.6, hole 0.3, Top Layer to Bottom Layer, tented both sides, 32 vias

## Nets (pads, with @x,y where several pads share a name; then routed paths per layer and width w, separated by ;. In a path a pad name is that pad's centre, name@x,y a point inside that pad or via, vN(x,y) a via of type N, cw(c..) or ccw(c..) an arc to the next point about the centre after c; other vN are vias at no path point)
3V3: C118.2 C200.2 C201.1 C400.2 C401.1 C413.1 C419.2 C422.2 C423.2 CON200.20 P200.3 R401.2 R414.2 R418.1 R419.2 TP113.1 U105.5 U400.4 U400.11 U402.8 U403.1 | length 103.1
  Top Layer w0.3: v1(-9.782,46.366) -9.763,46.347 -9.097,46.347 U403.1@-9.05,46.3 ; P200.3@-8.25,26.4 -6.093,26.4 C200.2@-6.075,26.382
  Top Layer w0.5: v1(-14.959,13.749) -11.351,13.749 -8.556,16.544 v2@-8.556,17.471
  Signal3 w0.3: v1(-24.913,27.025) -16.046,27.025 -15.821,27.251 v1(-15.794,27.251)
  Signal3 w0.5: v1(-9.993,35.923) -7.239,35.922 ; v1(-9.993,35.923) -9.993,35.99 -10.647,36.645 -10.647,45.501 v1(-9.782,46.366) ; v2@-8.548,17.464 v2(-8.563,17.478) -8.544,17.497 -8.544,18.033 -6.785,19.792 -6.785,25.806 ; P200.3@-8.25,26.4 -8.196,26.346 -7.324,26.346 ; -7.042,26.346 -7.324,26.346 ; -6.727,35.595 -6.4,35.922 ; v1@-5.725,36.02 -5.823,35.922 -6.4,35.922 ; -7.324,26.346 -6.785,25.806 ; -7.324,26.346 -6.785,26.885 ; -7.239,35.922 -6.785,35.468 -6.785,26.885 ; -7.239,35.922 -6.4,35.922 ; -6.785,25.806 -6.785,26.885
  Bottom Layer w0.2: U400.4@-6.7,37.5 -6.251,37.5 ; -5.832,37.248 -5.941,37.248 -5.97,37.277 ; C401.1@-5.65,37.3 C401.1@-5.627,37.277 ; -5.6,36.875 -5.787,37.055 -5.944,37.205 ; -5.6,36.951 -5.854,37.205 -5.944,37.205 ; C401.1@-5.6,37.25 C401.1@-5.627,37.277 ; -6.251,37.5 -6.019,37.277 ; -6.251,37.5 -6.193,37.5 -5.97,37.277 ; -6.019,37.277 -5.97,37.277 ; -6.019,37.277 -5.944,37.205 ; -5.97,37.277 C401.1@-5.627,37.277
  Bottom Layer w0.3: CON200.20@-27.385,6.088 -27.385,6.628 -28.012,7.255 C201.1@-28.012,7.454 -28.012,8.138 -26.987,9.163 -21.187,9.163 -20.213,10.137 -17.088,10.137 -16.543,10.682 C118.2@-16.543,12.291 ; v1@-24.879,27.018 -24.897,27 R419.2@-25.3,27 C423.2@-25.3,27.6 -25.23,27.67 U402.8@-23.875,27.67 ; R418.1@-16.8,25.85 -16.441,25.85 -15.825,26.467 -15.825,26.858 ; R401.2@-10.975,16.534 -10.978,16.537 -10.978,17.322 -10.683,17.617 -8.783,17.617 -8.644,17.478 v2(-8.563,17.478) ; C413.1@-10.575,36.675 C413.1@-10.575,36.675 ; U400.11@-10.021,37.054 -10.401,36.674 C413.1@-10.575,36.675 ; v1(-9.993,35.923) -10.006,35.936 -10.455,35.936 -10.537,36.019 -10.537,36.637 C413.1@-10.575,36.675 ; v1(-9.782,46.366) -9.755,46.366 -9.585,46.536 -8.626,46.536 R414.2@-8.596,46.506 C422.2@-8.596,47.081 ; P200.3@-8.25,26.4 -9.386,26.4 -10.194,27.207 -15.475,27.207 ; v1(-5.698,36.031) -5.687,36.043 -5.687,36.513 C400.2@-5.675,36.525 -5.6,36.6 -5.6,36.875 ; -5.6,36.951 C401.1@-5.6,37.25 ; -15.825,26.858 -15.475,27.207 ; -15.825,26.858 -15.825,27.17 -15.813,27.182 -15.813,27.232 v1(-15.794,27.251) -15.774,27.232 -15.499,27.232 -15.475,27.207
  Bottom Layer w0.5: U105.5@-17.793,12.291 -16.543,12.291 -15.565,12.291 -15.272,12.584 -15.272,13.435 v1(-14.959,13.749)
ADC1: C112.2 R125.1 R126.2 U102.96 | length 36
  Top Layer w0.18: R125.1@-26.45,9.625 -25.819,9.625 R126.2@-25.125,9.625 ; R126.2@-25.125,9.636 -24.659,9.636 -23.945,10.35 v1(-13.402,10.35) ; U102.96@-12.375,30.825 -12.171,31.029 v1(-12.171,31.371)
  Signal3 w0.18: v1(-13.402,10.35) -11.724,12.028 -11.724,26.405 -12.323,27.004 -12.323,31.159 -12.171,31.311 v1(-12.171,31.371)
ADC_CTRL: Q101.B U102.25 | length 35.2
  Top Layer w0.18: Q101.B@-25.65,11.375 -25.163,11.375 -24.613,10.825 -15.666,10.825 -15.625,10.866 -15.492,10.866 v1(-15.45,10.908) ; U102.25@-16.075,32.475 -15.888,32.662 -15.888,33.207 v1@-15.603,33.491
  Siganl4 w0.18: v1(-15.603,33.497) -15.603,32.797 -14.551,31.746 -14.551,23.837 -14.359,23.644 -14.359,11.999 v1(-15.45,10.908)
AGND: C413.2 C416.1 C417.1 C418.1 C419.1 C420.2 C421.1 C422.1 R413.1 R416.1 U400.0 U400.10 U403.2 U403.3 | length 10.3
  Top Layer w0.3: v1(-9.714,48.267) -9.697,48.283 -9.067,48.283 U403.2@-9.05,48.3 ; v1(-8.102,47.616) -8.083,47.635 -8.083,48.167 U403.3@-7.95,48.3
  Bottom Layer w0.2: v1(-9.404,36.552) -9,36.552 U400.10@-9,36.4 ; v1@-9.386,36.482 U400.10@-9.082,36.482
  Bottom Layer w0.3: v1(-11.735,35.983) -11.275,35.983 -11.235,35.943 -11.235,35.55 -11.288,35.497 v1(-11.288,35.487) ; v1(-11.661,36.673) -11.659,36.675 C413.2@-11.131,36.675 ; v1@-11.585,38.609 C418.1@-11.134,38.609 ; v1@-11.58,39.233 C417.1@-11.133,39.233 ; C419.1@-11.275,35.95 -11.2,36.025 -11.2,36.157 -11.131,36.226 -11.131,36.669 C413.2@-11.125,36.675 ; C418.1@-11.144,38.619 C417.1@-11.144,39.206 ; C416.1@-9.566,40.914 -9.566,41.673 -9.563,41.675 -9.563,41.746 v1(-9.544,41.765) ; v1@-9.544,41.745 -9.544,41.792 -9.325,42.011 -9.325,42.775 -9.473,42.923 -9.473,43.292 v1(-9.492,43.312) ; v1@-8.1,47.65 -8.096,47.646 C422.1@-8.096,47.081 -7.946,46.931 C420.2@-7.946,46.506 ; C421.1@-6.625,42.275 -6.625,42.69 v1(-6.622,42.693)
  other v1: -8.246,37.372 -8.711,37.785 -7.737,37.792 -11.598,38.623 -11.589,39.224 -2.973,41.467 -3.458,42.087 -3.185,43.415 -8.494,44.425 -9.65,45.236 -6.625,46.361 -6.575,47.986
